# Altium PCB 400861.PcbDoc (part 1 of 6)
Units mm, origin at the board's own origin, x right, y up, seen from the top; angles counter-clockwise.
Board outline 145 x 63.5 mm, 8 copper layers (Top Side, Mid-Layer 1, Mid-Layer 2, Mid-Layer 3, Mid-Layer 4, Mid-Layer 5, Mid-Layer 6, Bottom Side), stack 1.529 mm thick; 284 components, 233 nets, 1158 pads, 3522 vias.
Unrouted connection lines stored in the file: 1.
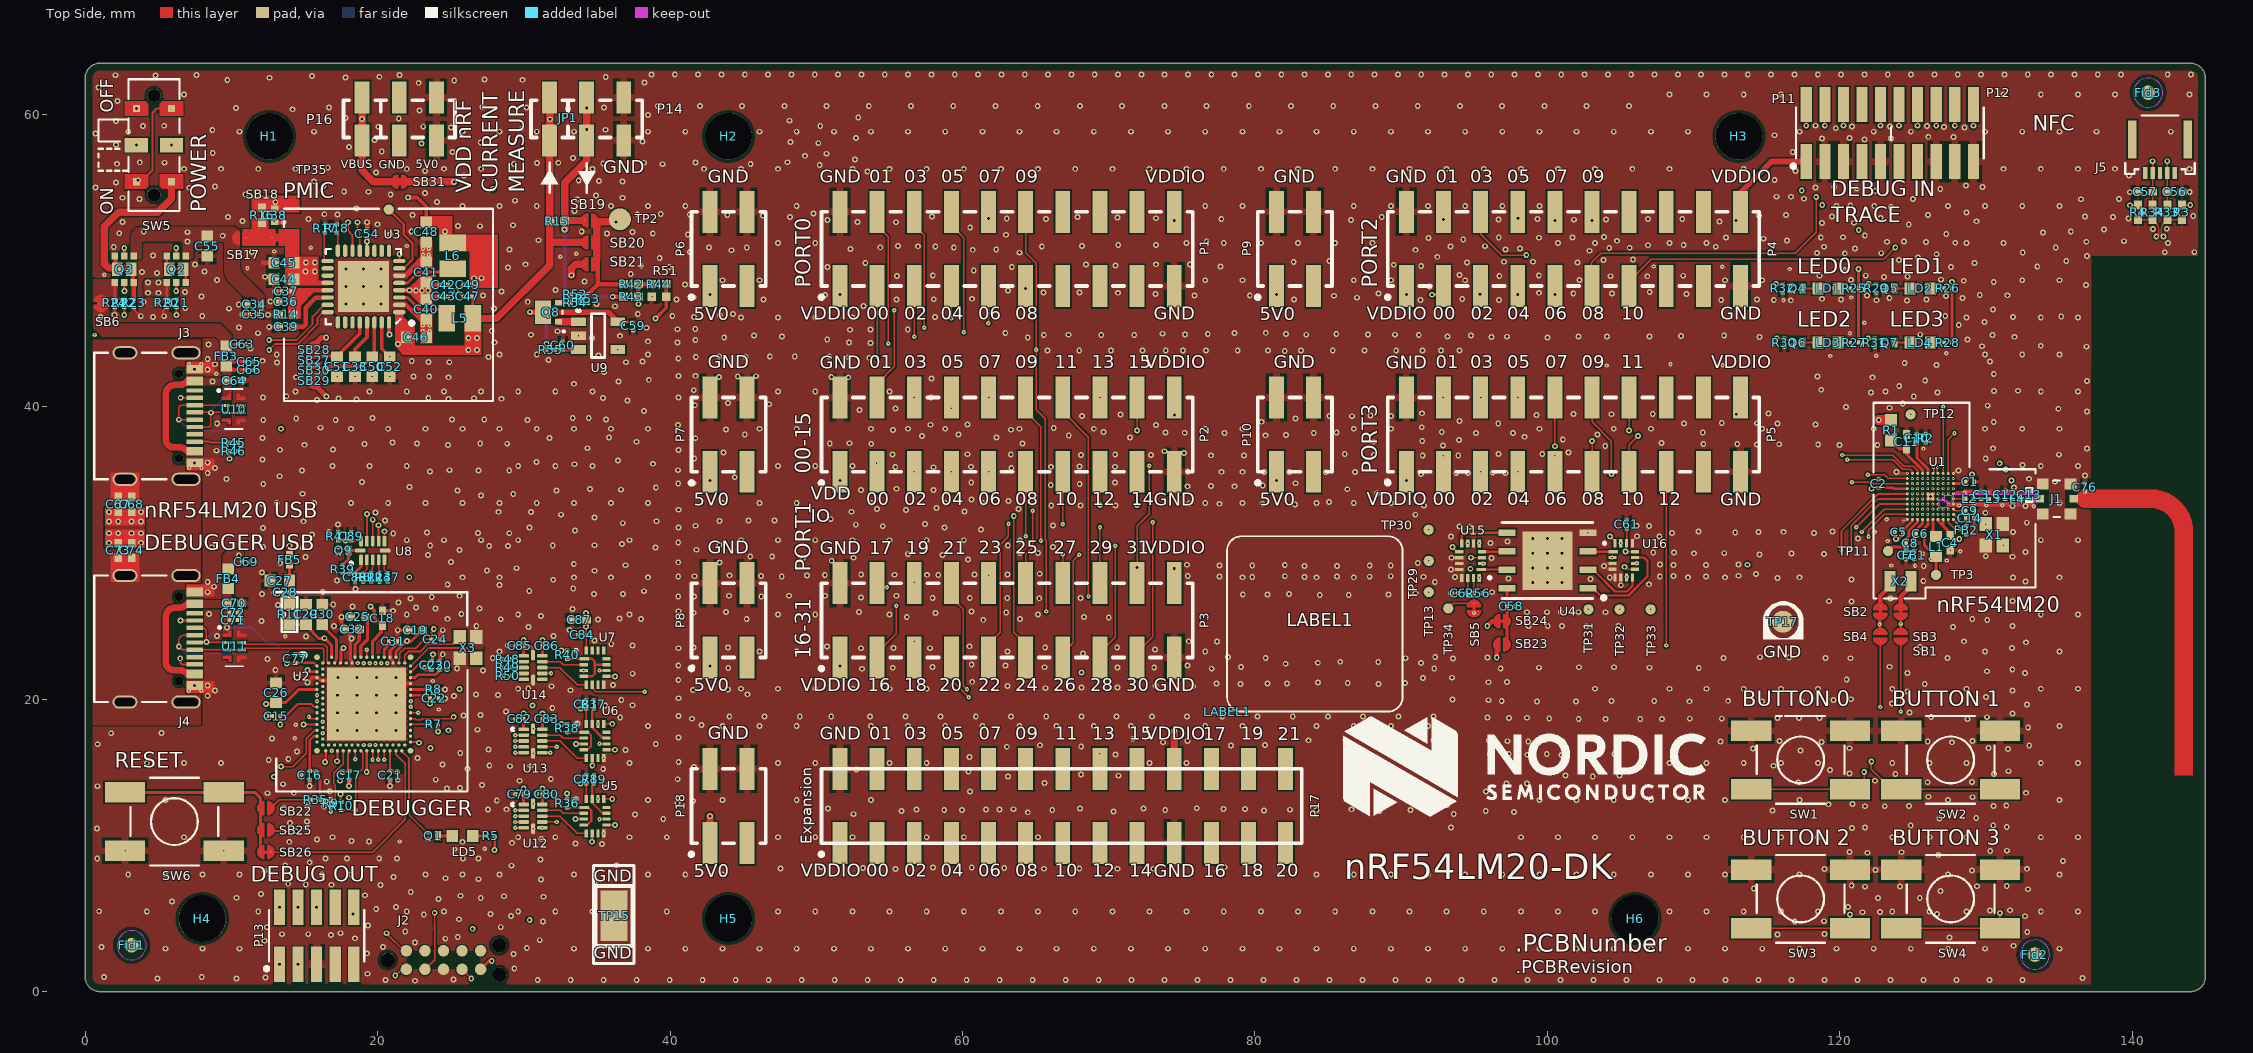
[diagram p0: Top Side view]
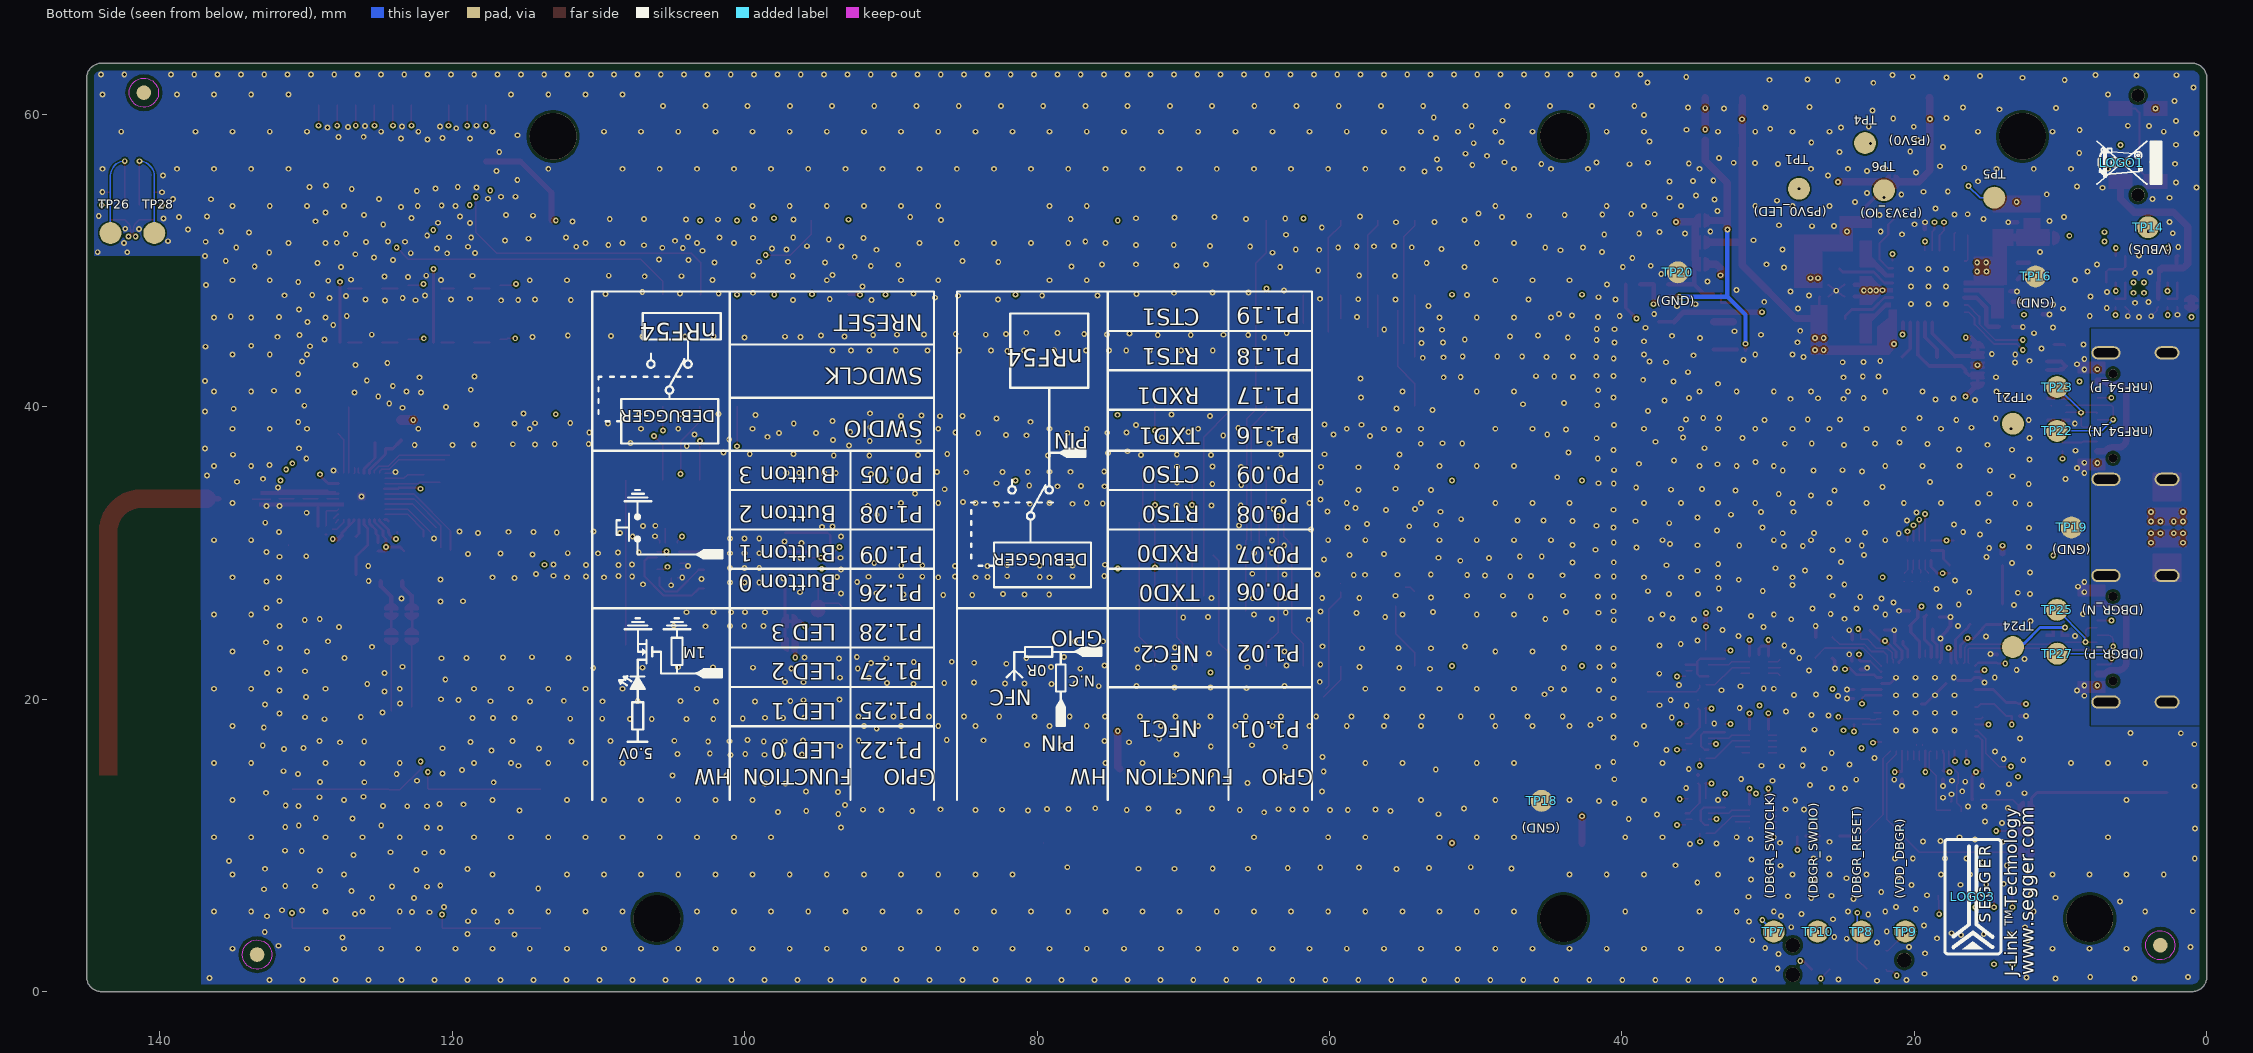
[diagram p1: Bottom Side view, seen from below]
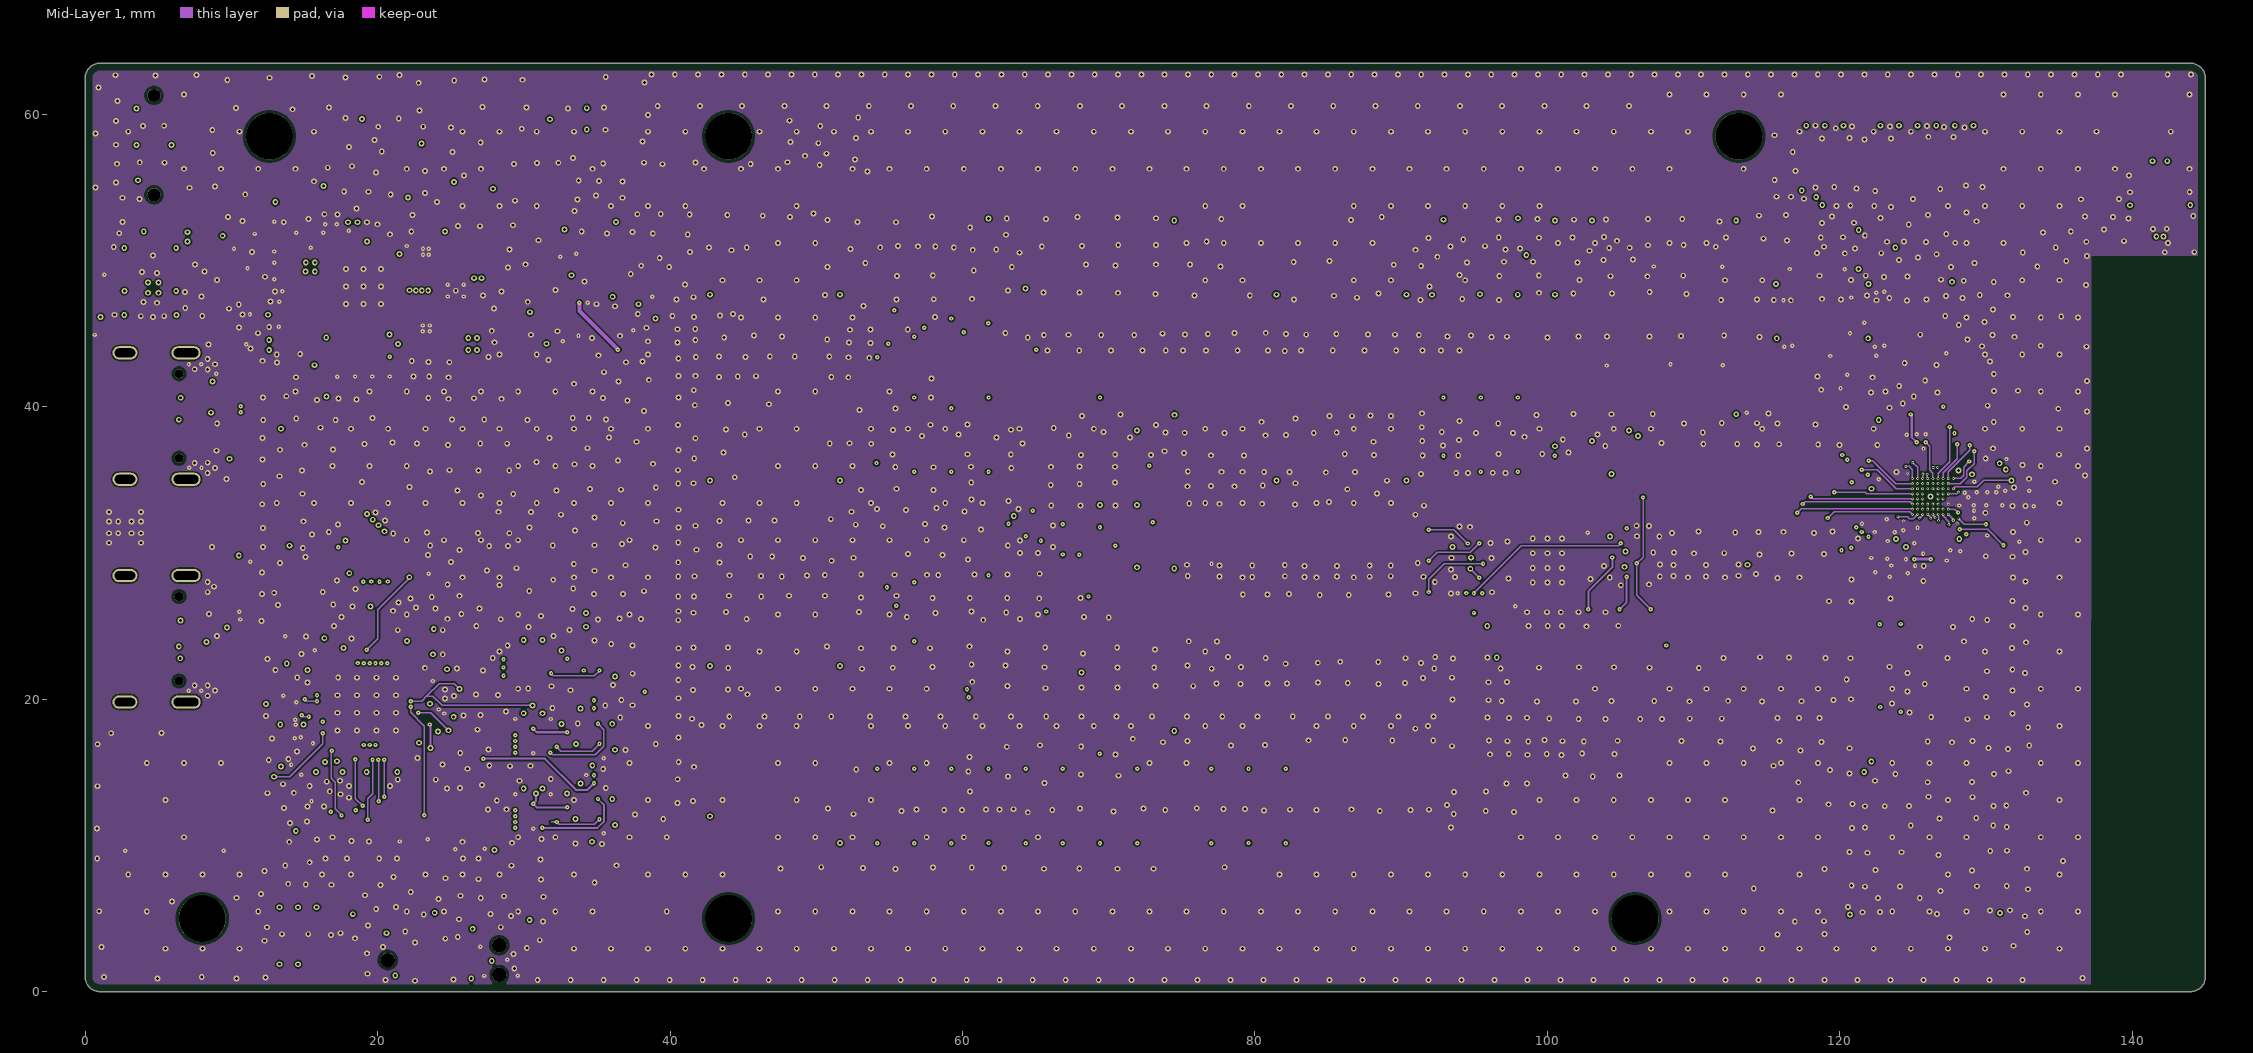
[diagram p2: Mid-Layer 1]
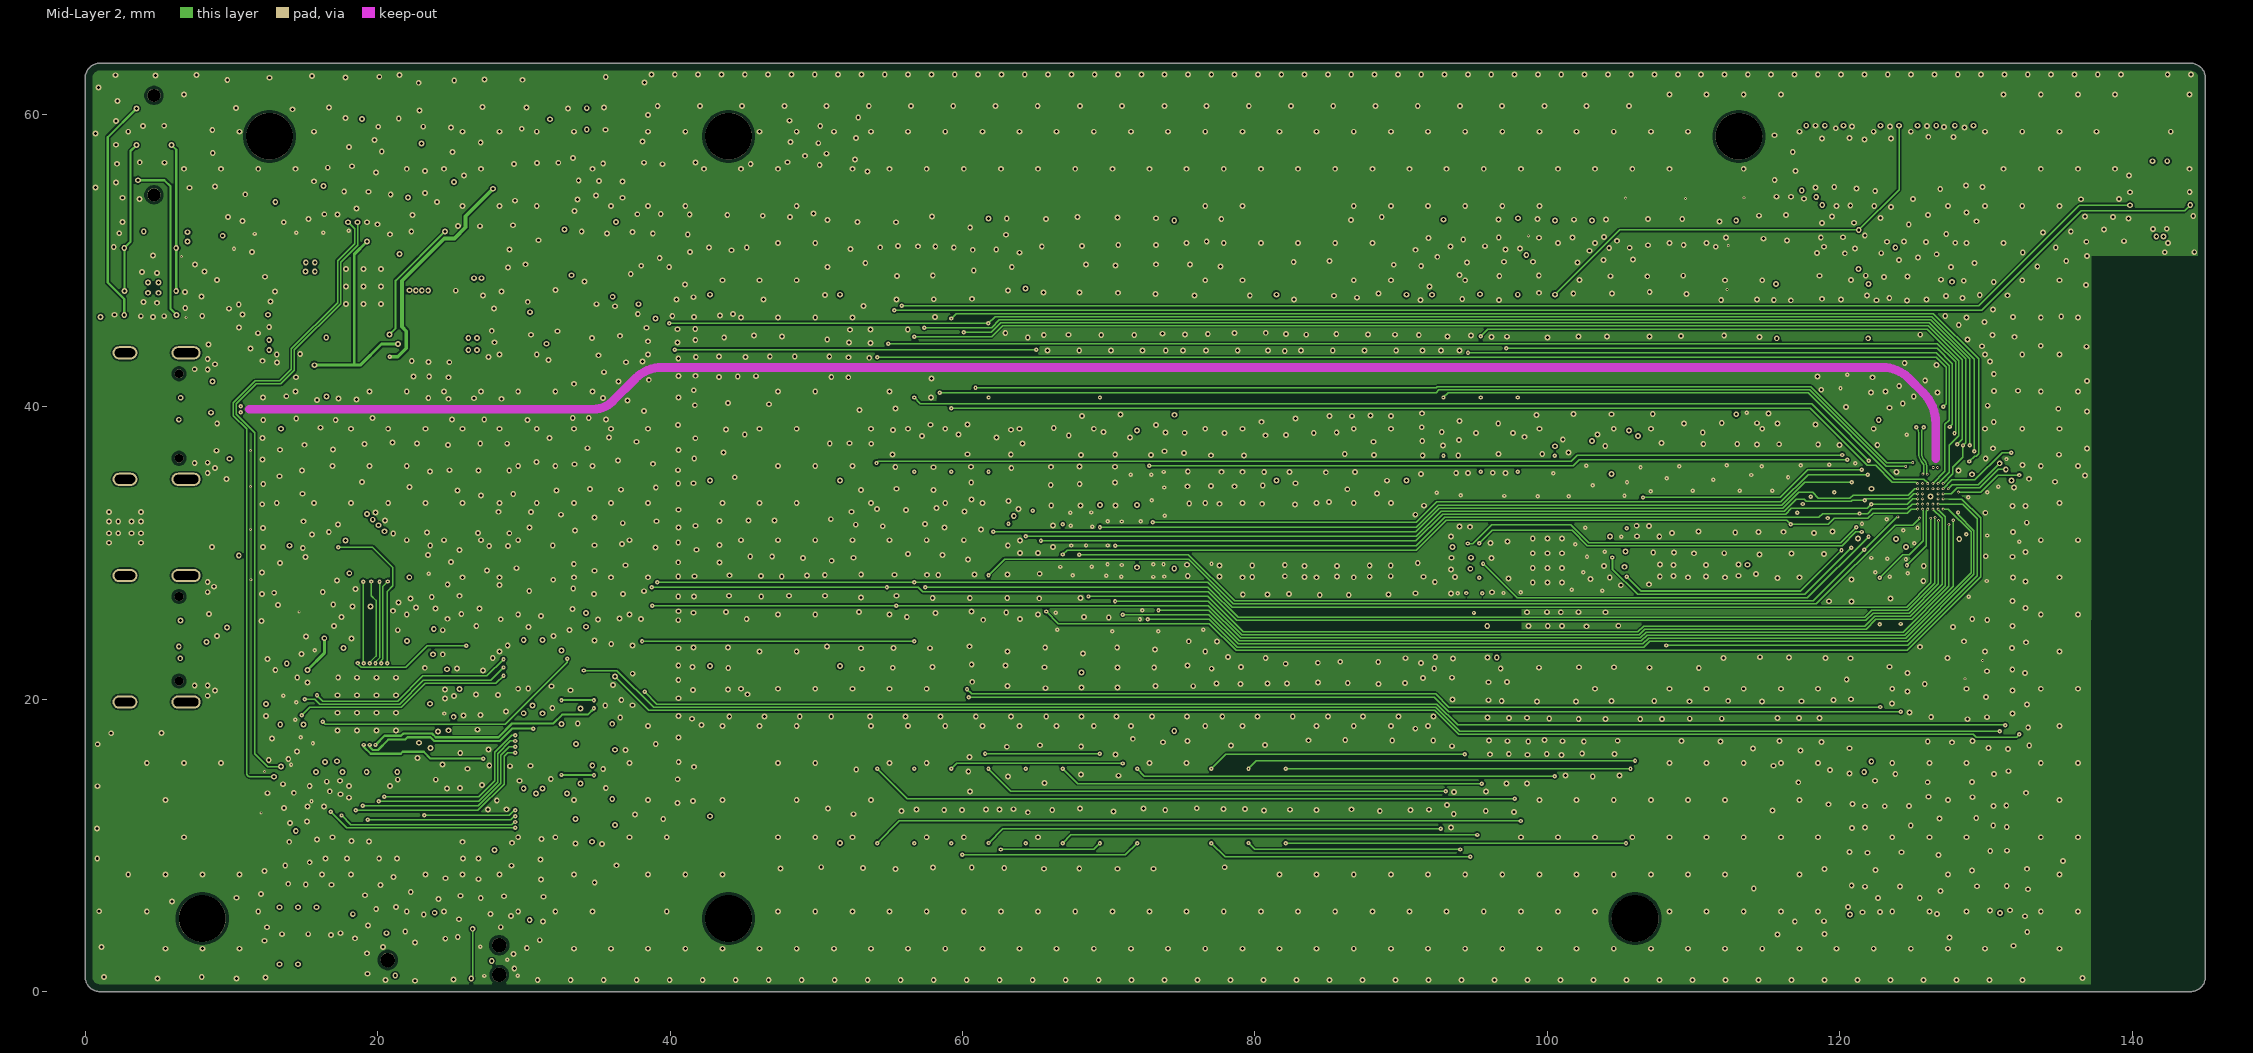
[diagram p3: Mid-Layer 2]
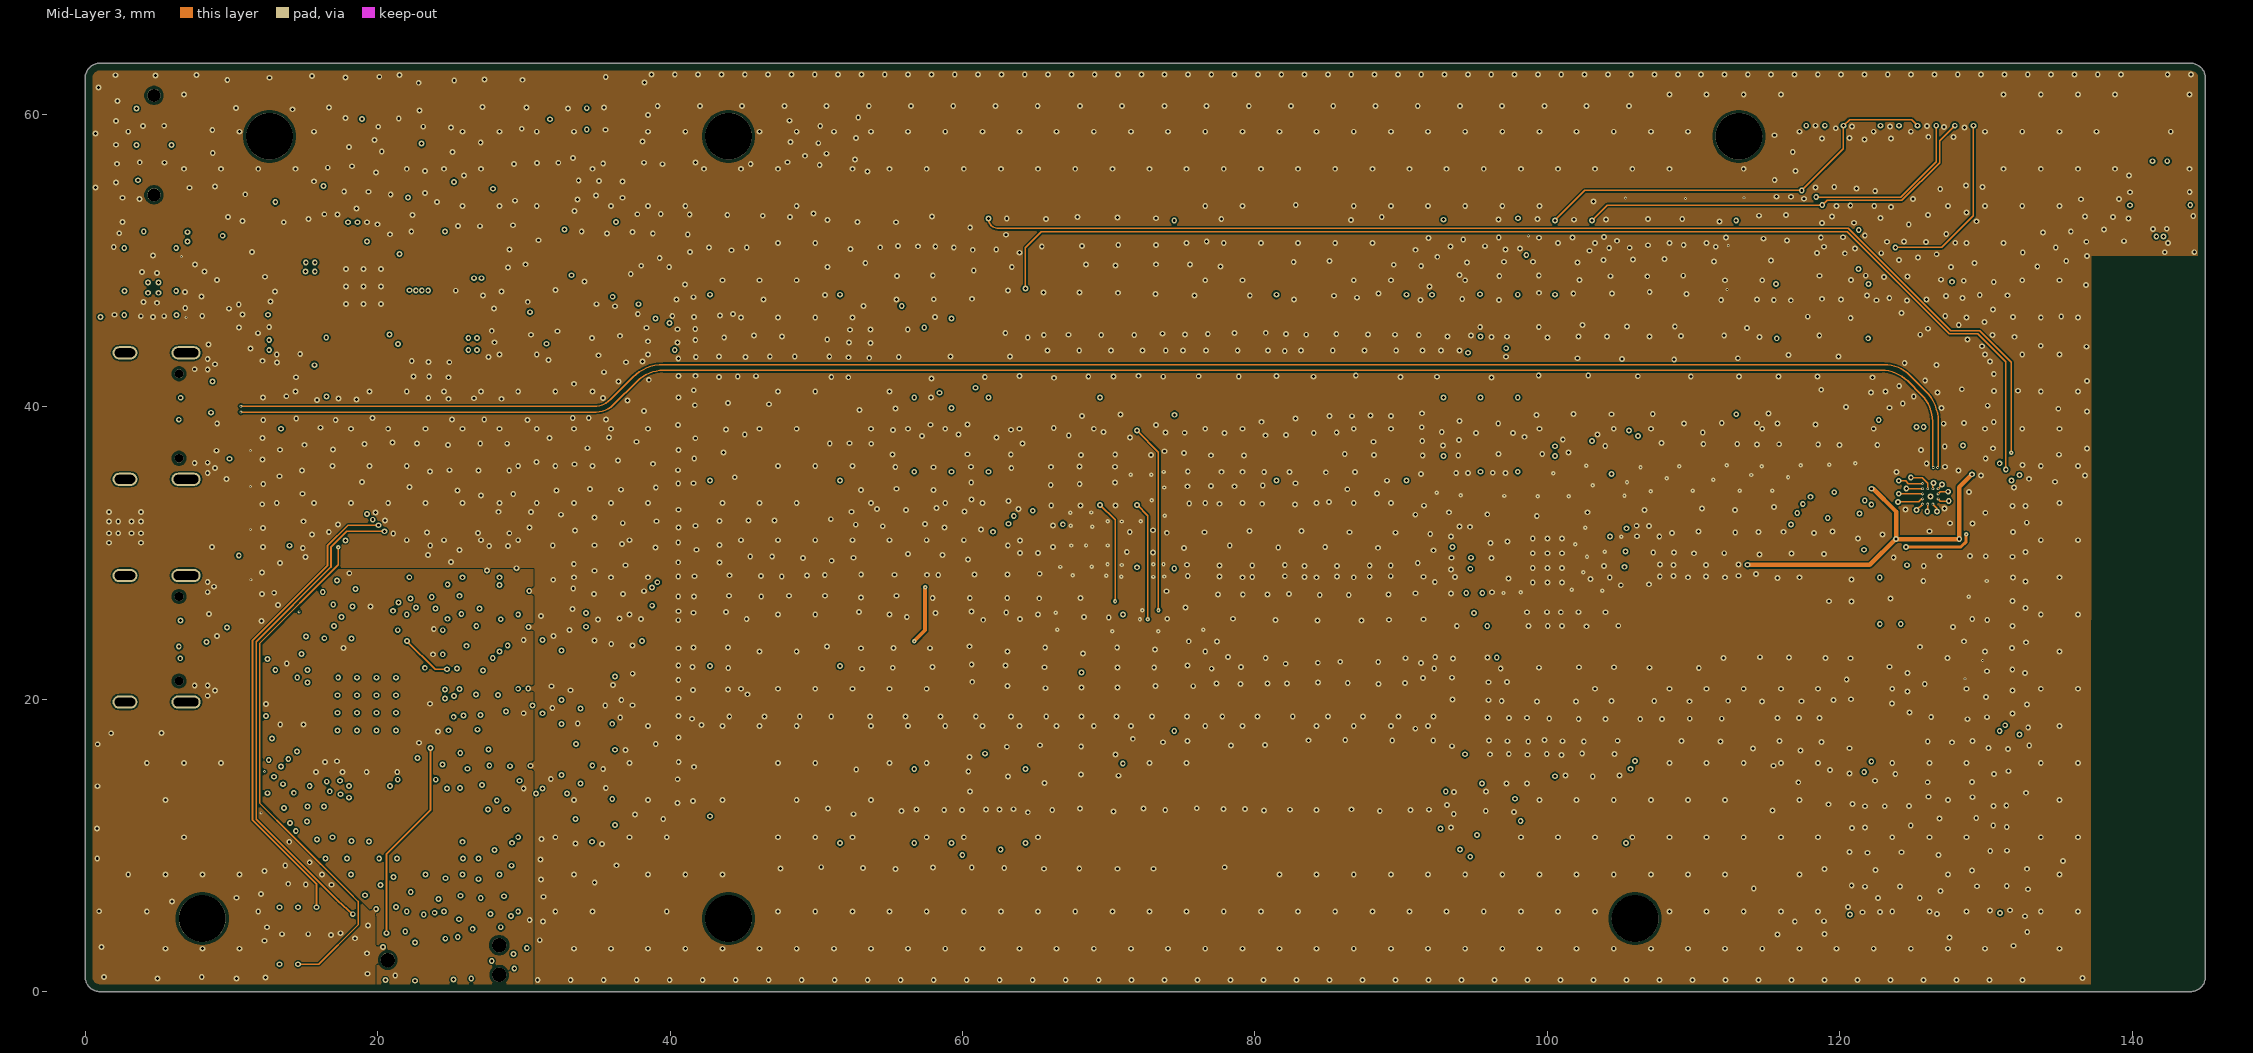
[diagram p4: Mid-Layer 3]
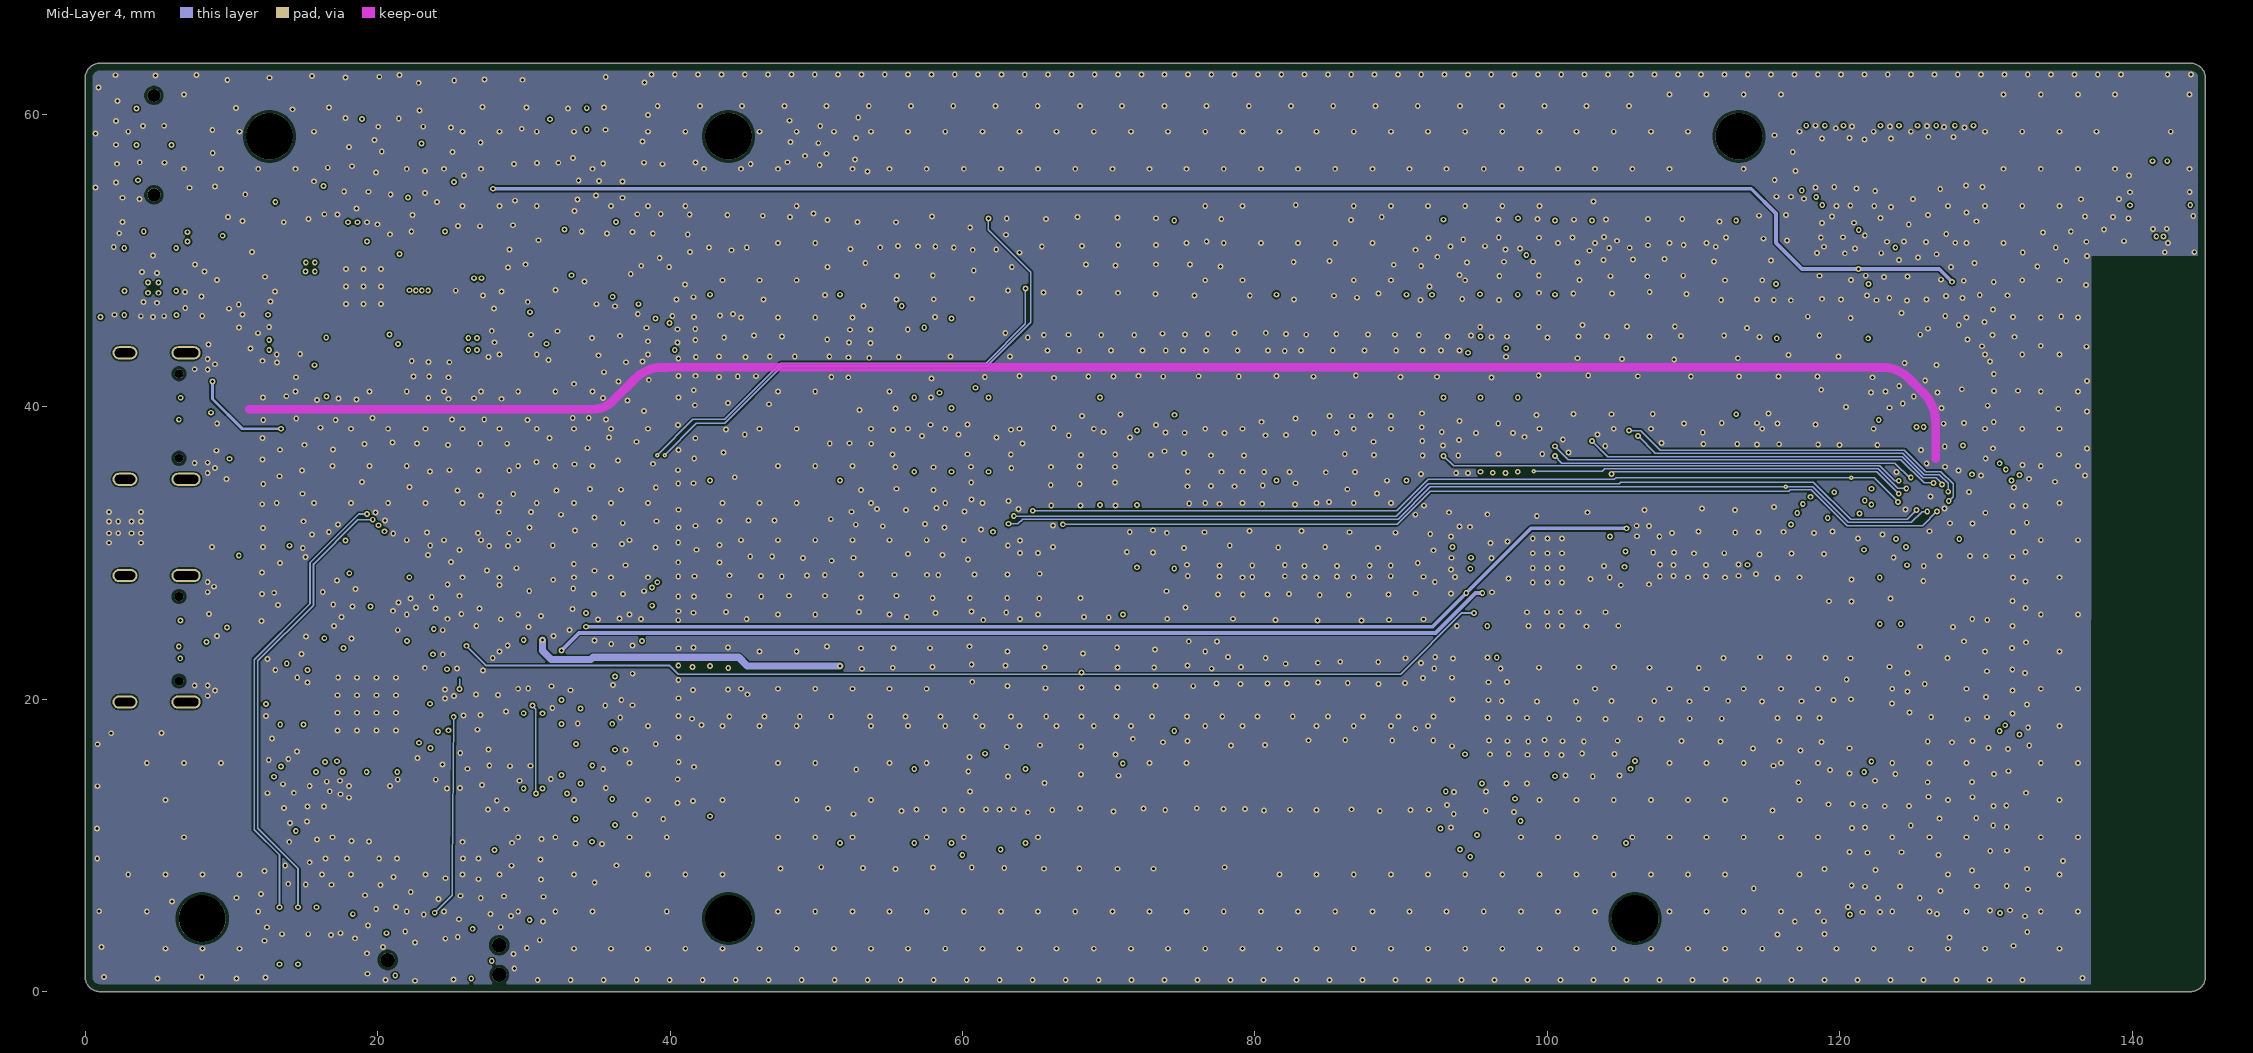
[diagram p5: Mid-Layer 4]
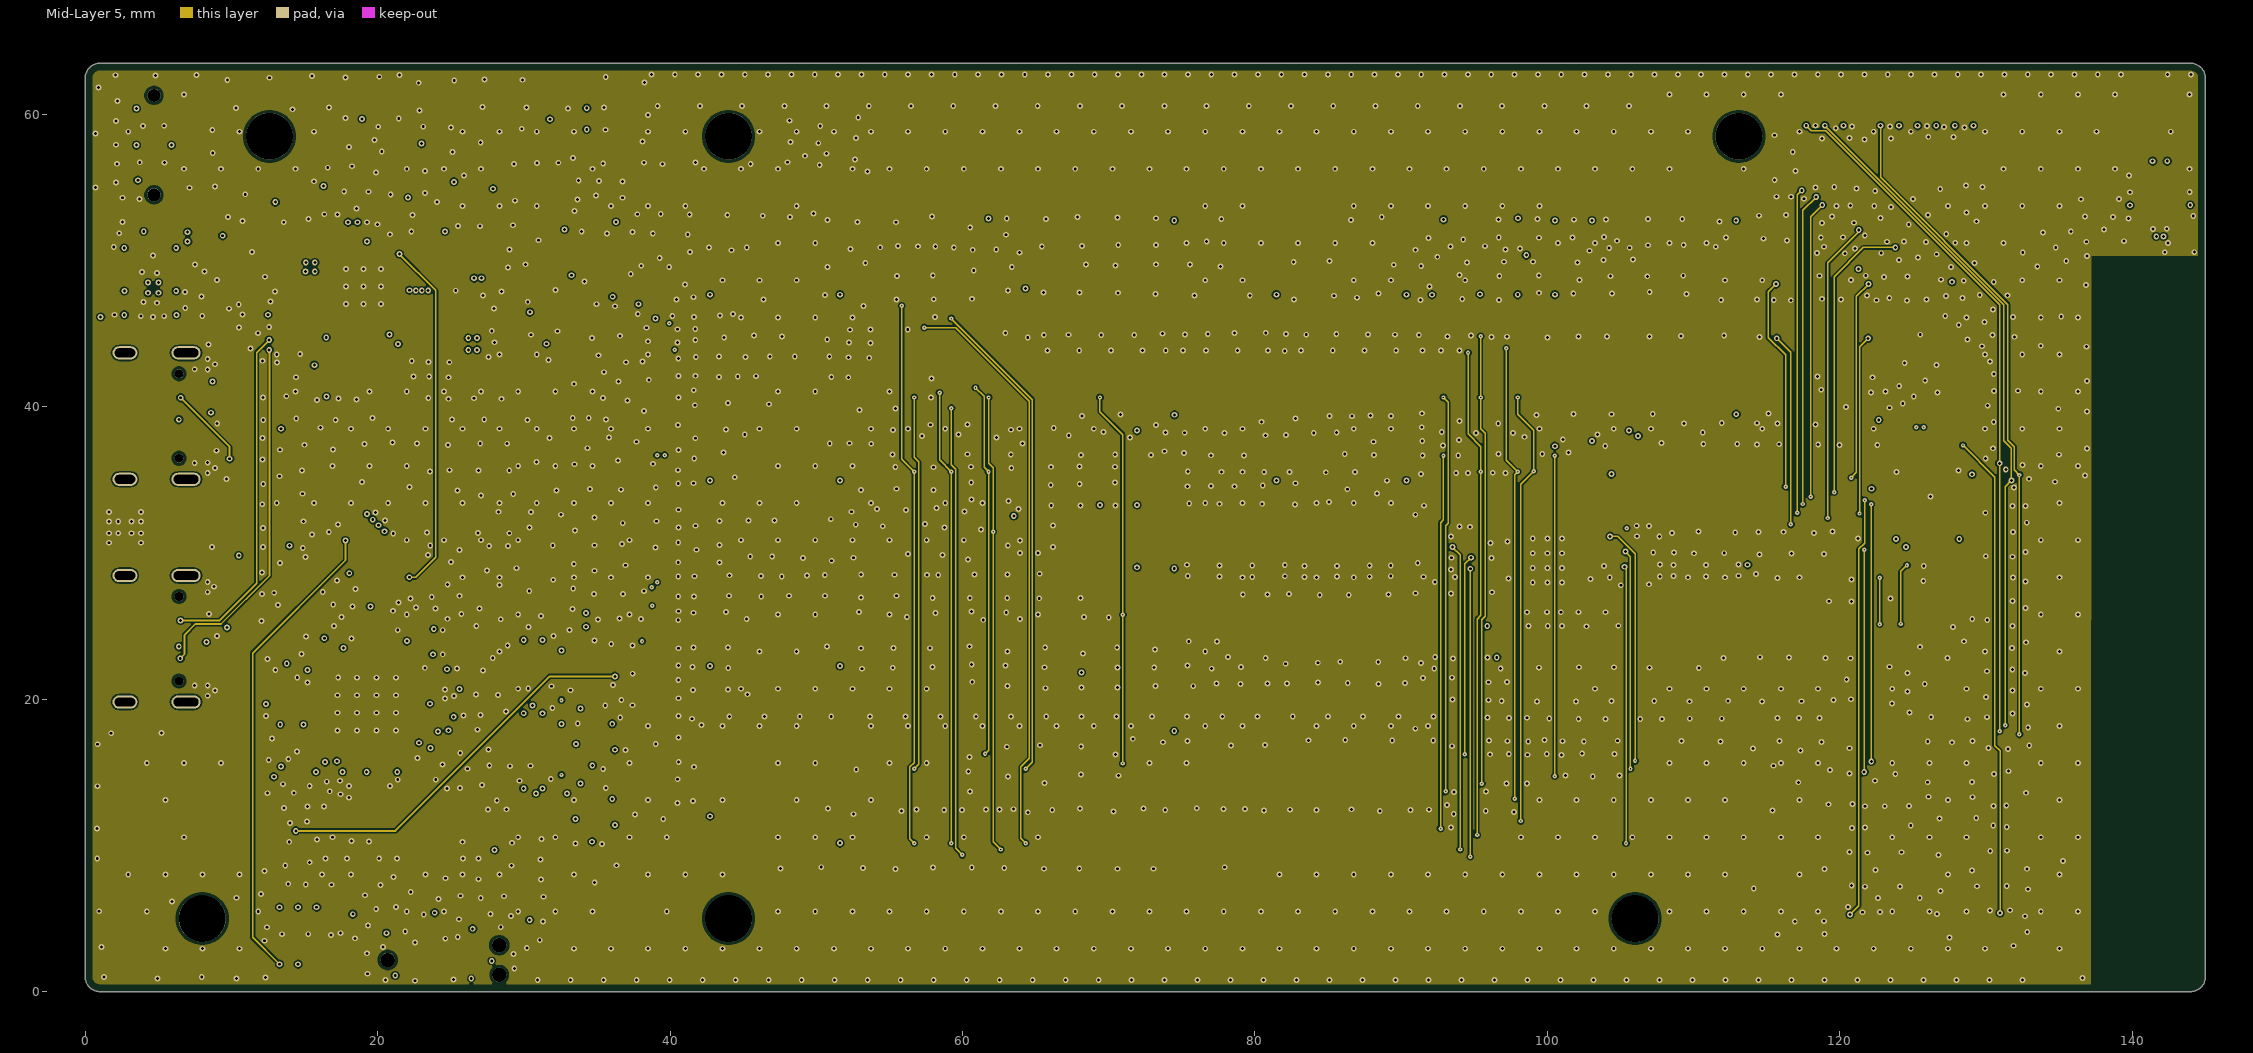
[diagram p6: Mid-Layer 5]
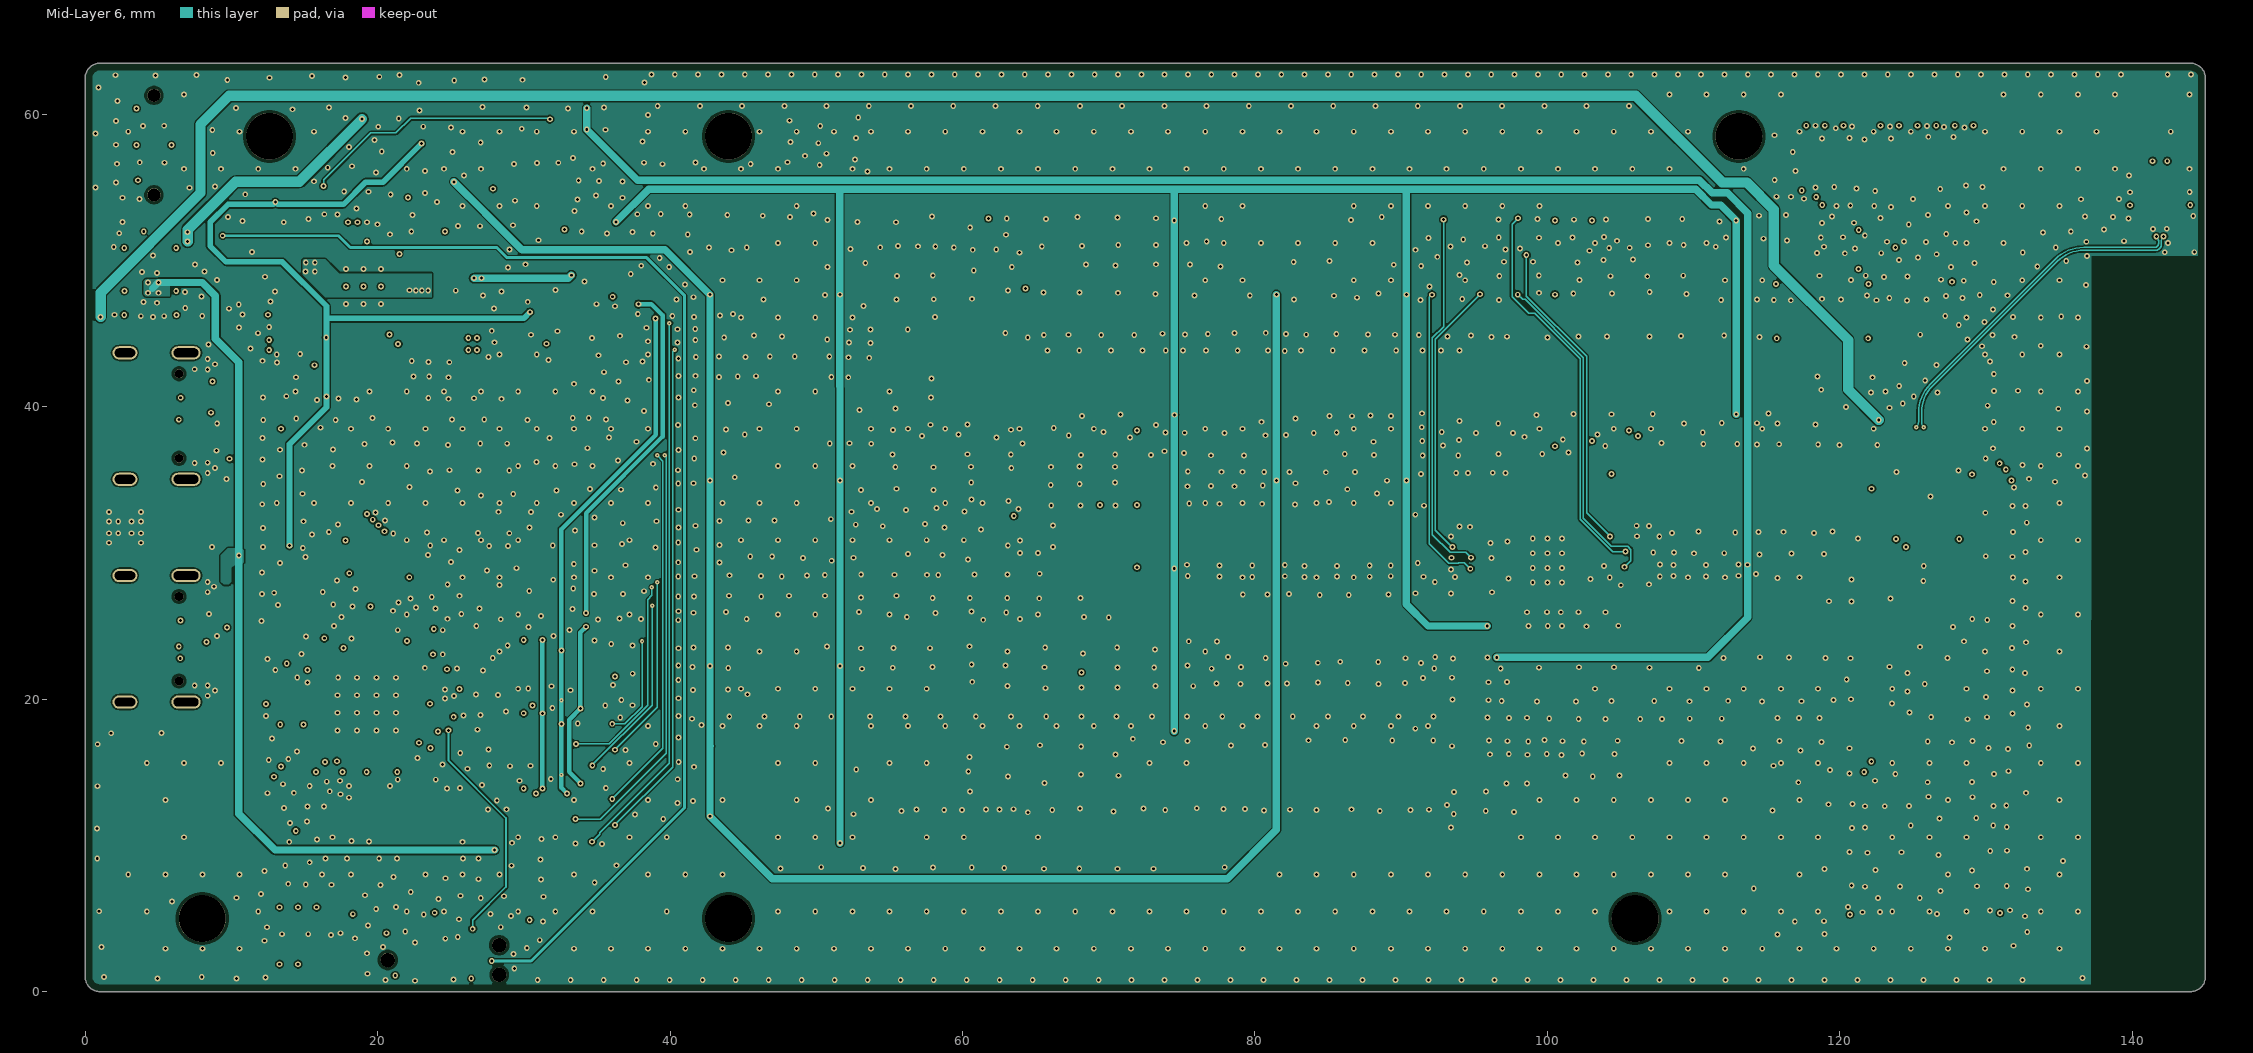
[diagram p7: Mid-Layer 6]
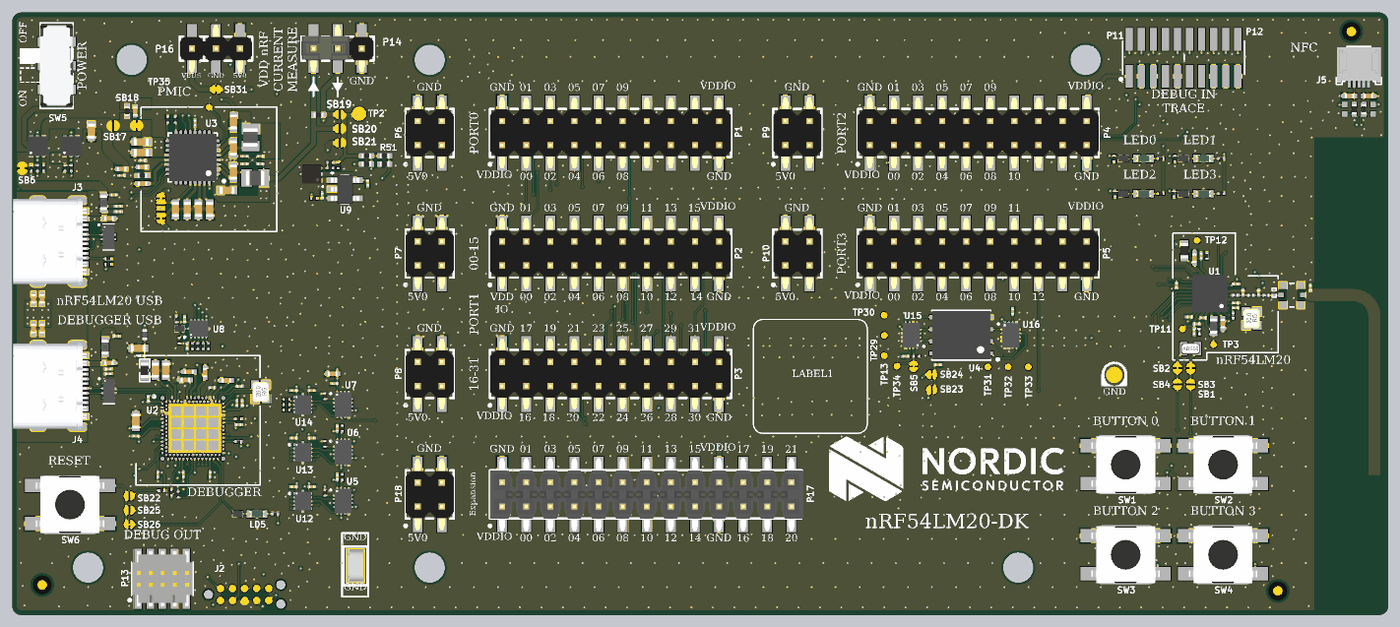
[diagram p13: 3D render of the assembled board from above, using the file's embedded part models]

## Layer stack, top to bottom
Top Solder: solder mask 0.015, WE-SM-0001, Dk 3.3
Top Side: signal copper 0.035
Dielectric 1: prepreg 0.07, WE-PP-0034, Dk 4.3
Mid-Layer 1: signal copper 0.025
Dielectric 2: prepreg 0.07, WE-PP-0034, Dk 4.3
Mid-Layer 2: signal copper 0.025
Dielectric 3: prepreg 0.07, WE-PP-0034, Dk 4.3
Mid-Layer 3: signal copper 0.025
Core 1: core 0.889, Core-041, Dk 4.8
Mid-Layer 4: signal copper 0.025
Dielectric 4: prepreg 0.07, WE-PP-0034, Dk 4.3
Mid-Layer 5: signal copper 0.025
Dielectric 5: prepreg 0.07, WE-PP-0034, Dk 4.3
Mid-Layer 6: signal copper 0.025
Dielectric 6: prepreg 0.07, WE-PP-0034, Dk 4.3
Bottom Side: signal copper 0.035
Bottom Solder: solder mask 0.015, WE-SM-0001, Dk 3.3

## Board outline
0,1 0,62.5 cw(c1,62.5) 1,63.5 144.002,63.5 144.002,63.499 cw(c144.002,62.5) 145,62.5 145,1 cw(c144,1) 144,0 1.001,0 1,0 cw(c1,1)

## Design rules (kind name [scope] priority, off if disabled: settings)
BoardOutlineClearance [All] p1: gap=0.25 ignorepadtopadclearanceinfootprint=FALSE except(0: Arc-SplitContinuation Track-SplitContinuation SMDPad-SplitContinuation THPad-SplitContinuation Via-SplitContinuation Fill-SplitContinuation Poly-SplitContinuation Region-SplitContinuation Text-SplitContinuation; 0.5: Arc-OutlineEdge Track-OutlineEdge SMDPad-OutlineEdge THPad-OutlineEdge Via-OutlineEdge Fill-OutlineEdge Poly-OutlineEdge Region-OutlineEdge Text-OutlineEdge)
Clearance Clearance_fid [InComponent('Fid1')or InComponent('Fid2')or InComponent('Fid3')] p1: gap=0.1 ignorepadtopadclearanceinfootprint=FALSE except(0.25: Arc-Fill Arc-Poly Arc-Region Track-Fill Track-Poly Track-Region SMDPad-Fill SMDPad-Poly SMDPad-Region THPad-Fill THPad-Poly THPad-Region Via-Fill Via-Poly Via-Region Fill-Fill Fill-Poly Fill-Region Poly-Poly Poly-Region Region-Region)
Clearance Clearance_keepout [IsKeepOut] p2: gap=0 ignorepadtopadclearanceinfootprint=FALSE
Clearance Clearance_54L20_room [InComponentClass('nRF54L20')] p3: gap=0.09 ignorepadtopadclearanceinfootprint=FALSE
Clearance "Antenna RF path clearance" [InNetClass('RF')] p4: gap=0.108 ignorepadtopadclearanceinfootprint=FALSE
Clearance "GND polygons" [InPolygonClass('GND')] p5: gap=0.15 ignorepadtopadclearanceinfootprint=FALSE
Clearance Clearance_NPTH [(HoleDiameter > 0) and (PadIsPlated = 'False')] p6: gap=0.254 ignorepadtopadclearanceinfootprint=FALSE except(0.2: Arc-Hole Track-Hole SMDPad-THPad SMDPad-Hole Fill-Hole Poly-Hole Region-Hole)
Clearance "Schematic Clearance Constraint_5" [InComponent('H6')] p7: gap=0.254 ignorepadtopadclearanceinfootprint=TRUE except(0: Arc-Hole Track-Hole SMDPad-Hole THPad-Hole Via-Hole Fill-Hole Poly-Hole Region-Hole Text-Hole)
Clearance "Schematic Clearance Constraint_4" [InComponent('H1')] p8: gap=0.254 ignorepadtopadclearanceinfootprint=TRUE except(0: Arc-Hole Track-Hole SMDPad-Hole THPad-Hole Via-Hole Fill-Hole Poly-Hole Region-Hole Text-Hole)
Clearance "Schematic Clearance Constraint_3" [InComponent('H4')] p9: gap=0.254 ignorepadtopadclearanceinfootprint=TRUE except(0: Arc-Hole Track-Hole SMDPad-Hole THPad-Hole Via-Hole Fill-Hole Poly-Hole Region-Hole Text-Hole)
Clearance "Schematic Clearance Constraint_2" [InComponent('H3')] p10: gap=0.254 ignorepadtopadclearanceinfootprint=TRUE except(0: Arc-Hole Track-Hole SMDPad-Hole THPad-Hole Via-Hole Fill-Hole Poly-Hole Region-Hole Text-Hole)
Clearance "Schematic Clearance Constraint_1" [InComponent('H2')] p11: gap=0.254 ignorepadtopadclearanceinfootprint=TRUE except(0: Arc-Hole Track-Hole SMDPad-Hole THPad-Hole Via-Hole Fill-Hole Poly-Hole Region-Hole Text-Hole)
Clearance "Schematic Clearance Constraint" [InComponent('H5')] p12: gap=0.254 ignorepadtopadclearanceinfootprint=TRUE except(0: Arc-Hole Track-Hole SMDPad-Hole THPad-Hole Via-Hole Fill-Hole Poly-Hole Region-Hole Text-Hole)
Clearance [All] p13: gap=0.1 ignorepadtopadclearanceinfootprint=FALSE except(0: Region-Region; 0.051: Text-Text)
ComponentClearance "Jumper clearance" [All] p1 off: gap=0 collisioncheckmode=3 verticalgap=0 showdistances=FALSE checkcomponentboundary=TRUE
ComponentClearance "Solder bridge overlap" [All] p2 off: gap=0.254 collisioncheckmode=3 verticalgap=2540 showdistances=FALSE donotcheckwithout3dbody=TRUE checkcomponentboundary=TRUE
ComponentClearance [All] p3 off: gap=0 collisioncheckmode=3 verticalgap=2540 showdistances=TRUE
DiffPairsRouting DiffPairsRouting_NFC [InDifferentialPair('NFC')] p1: maxlimit=0.4 minlimit=0.1 mostfreqgap=0.1 toplayer_minwidth=0.1 toplayer_maxwidth=0.5 toplayer_prefwidth=0.1 midlayer1_minwidth=0.1 midlayer1_maxwidth=0.5 midlayer1_prefwidth=0.1 midlayer2_minwidth=0.1 midlayer2_maxwidth=0.5 midlayer2_prefwidth=0.1 midlayer3_minwidth=0.1 midlayer3_maxwidth=0.5 midlayer3_prefwidth=0.1 midlayer4_minwidth=0.1 midlayer4_maxwidth=0.5 midlayer4_prefwidth=0.1 midlayer5_minwidth=0.1 midlayer5_maxwidth=0.5 midlayer5_prefwidth=0.1 midlayer6_minwidth=0.1 midlayer6_maxwidth=0.5 midlayer6_prefwidth=0.1 bottomlayer_minwidth=0.1 bottomlayer_maxwidth=0.5 bottomlayer_prefwidth=0.1 maxuncoupledlength=12.7
DiffPairsRouting DiffPairsRouting_USB [InNetClass('USB')] p2: maxlimit=0.3 minlimit=0.127 mostfreqgap=0.3 toplayer_maxgap=0.127 toplayer_prefgap=0.127 toplayer_minwidth=0.099 toplayer_maxwidth=0.099 toplayer_prefwidth=0.099 midlayer1_maxgap=0.127 midlayer1_prefgap=0.127 midlayer1_minwidth=0.049 midlayer1_maxwidth=0.049 midlayer1_prefwidth=0.049 midlayer2_maxgap=0.127 midlayer2_prefgap=0.127 midlayer2_minwidth=0.049 midlayer2_maxwidth=0.049 midlayer2_prefwidth=0.049 midlayer3_mingap=0.3 midlayer3_minwidth=0.09 midlayer3_maxwidth=0.09 midlayer3_prefwidth=0.09 midlayer4_mingap=0.3 midlayer4_minwidth=0.09 midlayer4_maxwidth=0.09 midlayer4_prefwidth=0.09 midlayer5_maxgap=0.127 midlayer5_prefgap=0.127 midlayer5_minwidth=0.049 midlayer5_maxwidth=0.049 midlayer5_prefwidth=0.049 midlayer6_maxgap=0.127 midlayer6_prefgap=0.127 midlayer6_minwidth=0.049 midlayer6_maxwidth=0.049 midlayer6_prefwidth=0.049 bottomlayer_maxgap=0.127 bottomlayer_prefgap=0.127 bottomlayer_minwidth=0.099 bottomlayer_maxwidth=0.099 bottomlayer_prefwidth=0.099 impedanceprofiledriven=TRUE impedanceprofileid={92417A29-2017-4163-8AF2-36A2DA04E51D} impedanceprofilevalue=90.000000 maxuncoupledlength=12.7
Height [All] p1 off: minheight=0 maxheight=25.4 prefheight=12.7
HoleSize [All] p1: absolutevalues=TRUE maxlimit=5 minlimit=0.025 maxpercent=80.000 minpercent=20.000
HoleToHoleClearance HoleToHoleClearance_nRF54 [WithinRoom('nRF54L20')] p1: gap=0.1 allowstackedmicrovias=TRUE
HoleToHoleClearance [All] p2: gap=0.15 allowstackedmicrovias=TRUE
MatchedLengths "Schematic Matched Net Lengths" [InNetClass('TRACE')] p1: tolerance=25.4 checknetsindiffpair=FALSE checkdiffpairvsdiffpair=TRUE checkxsignals=TRUE checkothers=TRUE usedelayunits=TRUE delaytolerance=500.000000
MinimumSolderMaskSliver [All] p1: minsoldermaskwidth=0.1
PolygonConnect "VBUS polygons" [InNet('VBUS') or InNet('VBUS_nRF') or InNet('VBUS_DBGR')] p1: connectstyle=Direct reliefconductorwidth=0.25 reliefentries=4 polygonreliefangle="90 Angle" airgapwidth=0.15
PolygonConnect "GND Polygon and Vias" [IsVia and InNet('GND')] p2: connectstyle=Direct reliefconductorwidth=0.254 reliefentries=4 polygonreliefangle="90 Angle" airgapwidth=0.254
PolygonConnect "GND Polygon and connectors" [InNet('GND') and InComponent('P*')] p3: connectstyle=Relief reliefconductorwidth=0.5 reliefentries=4 polygonreliefangle="90 Angle" conductorbypadedge=TRUE mindistance=0.25 enablemindistance=TRUE airgapwidth=0.2
PolygonConnect "GND Polygon and switches" [InNet('GND') and InComponent('SW*')] p4: connectstyle=Relief reliefconductorwidth=0.5 reliefentries=4 polygonreliefangle="90 Angle" conductorbypadedge=TRUE mindistance=0.25 enablemindistance=TRUE airgapwidth=0.2
PolygonConnect PolygonConnect_1 [IsPad and not InNet('GND') vs IsPolygon] p5: connectstyle=Direct reliefconductorwidth=0.254 reliefentries=4 polygonreliefangle="90 Angle" airgapwidth=0.254
PolygonConnect "GND Polygon and components" [InNet('GND') and InComponent('R*') or InComponent('C*') or InNamedPolygon('GND_nRF54')] p6: connectstyle=Relief reliefconductorwidth=0.3 reliefentries=4 polygonreliefangle="90 Angle" conductorbypadedge=TRUE mindistance=0.25 enablemindistance=TRUE airgapwidth=0.2
PolygonConnect [All] p7: connectstyle=Direct reliefconductorwidth=0.254 reliefentries=4 polygonreliefangle="90 Angle" airgapwidth=0.254
RoomDefinition Flash [InComponentClass('Flash')] p1: confinementstyle=ConfineIn formatcopy=TRUE lockcomponents=FALSE outline 94.28,17.972 94.28,20.772 95.926,20.772 95.926,21.147 96.451,21.147 96.451,25.647 104.181,25.647 104.181,19.997 95.683,19.997 95.683,17.972
RoomDefinition nRF54 [InComponentClass('nRF54')] p2: confinementstyle=ConfineIn formatcopy=TRUE lockcomponents=FALSE outline 123.856,31.657 128.476,31.657 128.476,36.5 123.856,36.5
RoomDefinition "Power Switch" [InComponentClass('Power Switch')] p3: confinementstyle=ConfineIn formatcopy=TRUE lockcomponents=FALSE outline -0.056,53.17 -0.056,62.831 9.156,62.831 9.156,49.279 12.679,49.279 12.679,46.721 6.779,46.721 6.779,46.302 6.104,46.302 3.854,46.302 3.209,46.302 2.141,46.302 1.486,46.302 1.486,47.557 0.816,47.557 0.816,53.17
RoomDefinition "Current measurments" [InComponentClass('Current measurments')] p4: confinementstyle=ConfineIn formatcopy=TRUE lockcomponents=FALSE outline 30.081,58.98 30.081,62.231 30.109,62.231 30.109,63.351 38.491,63.351 38.491,57.52 33.505,57.52 33.505,55.695 31.095,55.695 31.095,57.52 30.109,57.52 30.109,58.98
RoomDefinition nPM1300 [InComponentClass('nPM1300')] p5: confinementstyle=ConfineIn formatcopy=TRUE lockcomponents=FALSE outline 9.694,50.696 9.694,52.404 11.395,52.404 11.395,54.306 13.25,54.306 13.25,55.585 20.794,55.585 20.794,56.093 22.089,56.093 22.089,59.318 24.647,59.318 24.647,56.194 29.168,56.194 29.168,53.636 27.591,53.636 27.591,44.568 24.129,44.568 24.129,43.946 20.805,43.946 20.805,41.695 20.604,41.695 20.604,40.64 18.396,40.64 18.396,41.521 18.271,41.521 18.271,42.396 15.946,42.396 15.946,44.821 12.527,44.821 12.527,45.816 10.771,45.816 10.771,46.346 10.446,46.346 10.446,50.696
RoutingVias RoutingVia_RF54L20 [WithinRoom('nRF54')] p1: holewidth=0.711 width=1.27 viastyle="Through Hole" minholewidth=0.711 minwidth=1.27 maxholewidth=0.711 maxwidth=1.27 useviatemplates=TRUE viatemplateguid#1={EEEC76CF-32D6-49DC-93D9-2D917E6DBA36} viatemplateguid#2={30F8C89D-5C5B-4339-859E-098A5C8AA5FD} viatemplateguid#3={3D985D34-457C-4E2A-A3DE-9B1BD65E1015} viatemplatename#1=v20h10 viatemplatename#2=v30h10m0 viatemplatename#3=v40h20m0mx0
RoutingVias RoutingVia_Blind [IsBlindVia] p2: holewidth=0.711 width=1.27 viastyle="Through Hole" minholewidth=0.711 minwidth=1.27 maxholewidth=0.711 maxwidth=1.27 useviatemplates=TRUE viatemplateguid#1={30F8C89D-5C5B-4339-859E-098A5C8AA5FD} viatemplatename#1=v30h10m0
RoutingVias RoutingVia_Burried [InDrillLayerPair('Mid-Layer 3 - Mid-Layer 4')] p3: holewidth=0.711 width=1.27 viastyle="Through Hole" minholewidth=0.711 minwidth=1.27 maxholewidth=0.711 maxwidth=1.27 useviatemplates=TRUE viatemplateguid#1={3D985D34-457C-4E2A-A3DE-9B1BD65E1015} viatemplatename#1=v40h20m0mx0
RoutingVias RoutingVia_Burried_laser [InDrillLayerPair('Mid-Layer 1 - Mid-Layer 2') or  InDrillLayerPair('Mid-Layer 2 - Mid-Layer 3') or InDrillLayerPair('Mid-Layer 4 - Mid-Layer 5') or  InDrillLayerPair('Mid-Layer 5 - Mid-Layer 6')] p4: holewidth=0.711 width=1.27 viastyle="Through Hole" minholewidth=0.711 minwidth=1.27 maxholewidth=0.711 maxwidth=1.27 useviatemplates=TRUE viatemplateguid#1={30F8C89D-5C5B-4339-859E-098A5C8AA5FD} viatemplatename#1=v30h10m0
RoutingVias RoutingVia_Thru [IsThruVia] p5: holewidth=0.25 width=0.5 viastyle="Through Hole" minholewidth=0.1 minwidth=0.2 maxholewidth=0.5 maxwidth=1.2 useviatemplates=TRUE viatemplateguid#1={3D985D34-457C-4E2A-A3DE-9B1BD65E1015} viatemplatename#1=v40h20m0mx0
RoutingVias "Schematic Routing Via Style_5" [InComponent('H5')] p6: holewidth=0 width=0 viastyle="Through Hole" minholewidth=0 minwidth=0 maxholewidth=2 maxwidth=2
RoutingVias "Schematic Routing Via Style_4" [InComponent('H1')] p7: holewidth=0 width=0 viastyle="Through Hole" minholewidth=0 minwidth=0 maxholewidth=2 maxwidth=2
RoutingVias "Schematic Routing Via Style_3" [InComponent('H6')] p8: holewidth=0 width=0 viastyle="Through Hole" minholewidth=0 minwidth=0 maxholewidth=2 maxwidth=2
RoutingVias "Schematic Routing Via Style_2" [InComponent('H4')] p9: holewidth=0 width=0 viastyle="Through Hole" minholewidth=0 minwidth=0 maxholewidth=2 maxwidth=2
RoutingVias "Schematic Routing Via Style_1" [InComponent('H2')] p10: holewidth=0 width=0 viastyle="Through Hole" minholewidth=0 minwidth=0 maxholewidth=2 maxwidth=2
RoutingVias "Schematic Routing Via Style" [InComponent('H3')] p11: holewidth=0 width=0 viastyle="Through Hole" minholewidth=0 minwidth=0 maxholewidth=2 maxwidth=2
ShortCircuit "GND to PVSS" [InNet('PVSS1') or InNet('PVSS2') vs InNet('GND')] p1: allowed=TRUE
ShortCircuit P11_P12 [InComponent('P11') vs InComponent('P12')] p2: allowed=TRUE
ShortCircuit [All] p3: allowed=FALSE
SolderMaskExpansion SolderMaskExpansion_Comp1 [HasFootprint('BGA98C35P10X10_367X385X86') or HasFootprint('AQFN40P700X700X85_HS-99N') or HasFootprint('XFDFN40P180X120X40-8M')] p1: expansion=0.025 istentingtop=FALSE
SolderMaskExpansion SolderMaskExpansion_Comp2 [HasFootprint('Nordic_QFN50P500X500X90-33N') or HasFootprint('SD-80259-001')] p2: expansion=0.05 istentingtop=FALSE
SolderMaskExpansion SolderMaskExpansion_Via [IsVia] p3: expansion=0.102 istentingtop=TRUE
SolderMaskExpansion [All] p4: expansion=0.102 istentingtop=FALSE
SupplyNets "Schematic Supply Nets_6" [InNet('5V0:CONN')] p1: voltage=0.000
SupplyNets "Schematic Supply Nets_15" [InNet('VDD:IO')] p2: voltage=0.000
SupplyNets "Schematic Supply Nets_14" [InNet('VDD:SW_PU')] p3: voltage=0.000
SupplyNets "Schematic Supply Nets_11" [InNet('VDD:nRF_PMIC')] p4: voltage=0.000
SupplyNets "Schematic Supply Nets_4" [InNet('VDD:SW')] p5: voltage=0.000
SupplyNets "Schematic Supply Nets_3" [InNet('P5V0:LED')] p6: voltage=0.000
SupplyNets "Schematic Supply Nets_7" [InNet('VDD:SWD0')] p7: voltage=0.000
SupplyNets "Schematic Supply Nets_10" [InNet('VBUS:DBGR')] p8: voltage=0.000
SupplyNets "Schematic Supply Nets_2" [InNet('VDD:nRF')] p9: voltage=0.000
SupplyNets "Schematic Supply Nets_13" [InNet('VDD:DBGR')] p10: voltage=0.000
SupplyNets "Schematic Supply Nets_12" [InNet('VBUS:nRF')] p11: voltage=0.000
SupplyNets "Schematic Supply Nets_9" [InNet('P5V0')] p12: voltage=0.000
SupplyNets "Schematic Supply Nets_8" [InNet('GND')] p13: voltage=0.000
SupplyNets "Schematic Supply Nets_5" [InNet('Shield')] p14: voltage=0.000
SupplyNets "Schematic Supply Nets_1" [InNet('VBUS')] p15: voltage=0.000
Width "Antena width" [InNet('ANT')] p1: maxlimit=2 minlimit=0.1 preferedwidth=0.254
Width "RF class" [InNetClass('RF')] p2: maxlimit=0.254 minlimit=0.102 preferedwidth=0.254 toplayer_maxwidth=0.102 toplayer_prefwidth=0.102 bottomlayer_maxwidth=0.102 bottomlayer_prefwidth=0.102 impedanceprofiledriven=TRUE impedanceprofileid={1565A465-2A4E-46A6-9374-F3DA2557FCC2} impedanceprofilevalue=50.000000 minimp=50.000000 maximp=50.000000 favimp=50.000000
Width [All] p3: maxlimit=1 minlimit=0.09 preferedwidth=0.1
23 further rules are at their usual default settings.

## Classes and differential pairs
component class Switches: C61 C62 R56 SB5 TP13 TP29 TP30 TP31 TP32 TP33 TP34 U15 U16
component class nRF54: U1
net class RF: ANT ant:1 ant:2 ant:3 ant:4
differential pair class NFC: NFC
component class "Power Switch": C55 Q2 Q3 R20 R21 R22 R23 R24 SB6 SW5 TP14
component class nPM1300: C33 C34 C35 C36 C37 C38 C39 C40 C41 C42 C43 C44 C45 C46 C47 C48 C49 C50 C51 C52 C54 L5 L6 R14 R16 R17 R18 SB17 SB18 SB20 SB21 SB27 SB28 SB29 SB30 TP1 TP4 TP5 TP6 TP35 U3
component class "Current measurments": JP1 P14 R15 SB19
component class Flash: C58 SB23 SB24 U4
net class TRACE: P2.06 P2.07 P2.08 P2.09 P2.10
component class "Levelshifters and switches": C78 C79 C80 C81 C82 C83 C84 C85 C86 C87 C88 C89 Q9 R19 R36 R37 R38 R39 R40 R41 R42 R43 R44 R51 U5 U6 U7 U8 U12 U13 U14
component class pca10184_top_level: SB25 SB26
component class Misc: C56 C57 C58 LD1 LD2 LD3 LD4 Q4 Q5 Q6 Q7 R25 R26 R27 R28 R29 R30 R31 R32 R33 R34 R35 SB22 SB23 SB24 SW1 SW2 SW3 SW4 SW6 U4
component class nRF54LM20: C1 C2 C3 C4 C5 C6 C7 C8 C9 C10 C11 C12 C13 C14 C76 FB1 FB2 J1 L1 L2 L3 L4 R1 R2 R3 R4 SB1 SB2 SB3 SB4 TP3 TP11 TP12 U1 X1 X2
differential pair class nRF54: DBGR_CON J2 J3 nRF54_CON
differential pair class IMCU: DBGR DBGR_U2 USB_nRF54
net class USB: DBGR_CON_N DBGR_CON_P DBGR_N DBGR_P nRF54_CON_N nRF54_CON_P USB_nRF54_D+ USB_nRF54_D-
net class UART1: UART1_CTRL UART1_CTS_DBGR UART1_HWFC UART1_RTS_DBGR UART1_RxD_DBGR UART1_TxD_DBGR
net class UART0: UART0_CTRL UART0_CTS_DBGR UART0_HWFC UART0_RTS_DBGR UART0_RxD_DBGR UART0_TxD_DBGR
component class "Power supply": C33 C34 C35 C36 C37 C38 C39 C40 C41 C42 C43 C44 C45 C46 C47 C48 C49 C50 C51 C52 C54 C55 C59 C60 JP1 L5 L6 P14 P16 Q2 Q3 Q8 R14 R15 R16 R17 R18 R20 R21 R22 R23 R24 R52 R53 R54 R55 SB6 SB17 SB18 SB19 SB20 SB21 SB27 SB28 SB29 SB30 SB31 SW5 TP1 TP2 TP4 TP5 TP6 TP14 TP15 TP16 TP17 TP18 TP19 TP20 TP35 U3 U9
component class Mechanical: Fid1 Fid2 Fid3 H1 H2 H3 H4 H5 H6 LABEL1 LOGO1 LOGO3
component class Debugger: C15 C16 C17 C18 C19 C20 C21 C22 C23 C24 C25 C26 C27 C28 C29 C30 C31 C32 C77 FB5 J2 LD5 Q1 R5 R6 R7 R8 R9 R10 R11 R12 R13 R47 R48 R49 R50 TP7 TP8 TP9 TP10 U2 X3
component class Connectors: C63 C64 C65 C66 C67 C68 C69 C70 C71 C72 C73 C74 FB3 FB4 J3 J4 J5 P1 P2 P3 P4 P5 P6 P7 P8 P9 P10 P11 P12 P13 P17 P18 P30 P31 P32 P34 P35 R45 R46 TP21 TP22 TP23 TP24 TP25 TP26 TP27 TP28 U10 U11
differential pair nRF54_CON: +nRF54_CON_P -nRF54_CON_N
differential pair USB_nRF54: +USB_nRF54_D+ -USB_nRF54_D-
differential pair NFC: +NFC_P -NFC_N
differential pair DBGR_CON: +DBGR_CON_P -DBGR_CON_N
differential pair DBGR: +DBGR_P -DBGR_N

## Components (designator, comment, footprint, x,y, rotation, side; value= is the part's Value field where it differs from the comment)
C1 "100nF" CAPC0603X03L_C 128.903,34.877 r0 top
C2 "100nF" CAPC0603X03L_C 122.674,34.751 r90 top
C3 "2.0pF" CAPC0603X03L_C 129.688,33.976 r270 top
C4 "10µF" CAPC1005X04L 127.552,30.702 r90 top
C5 "100nF" CAPC0603X03L_C 124.046,31.414 r180 top
C6 "2.2µF" CAPC0603X03L_C 125.494,31.312 r0 top
C7 "2.2µF" CAPC0603X03L_C 124.529,29.864 r90 top
C8 "10nF" CAPC0603X03L_C 124.808,30.677 r180 top
C9 "3.9pF" CAPC0603X03L_C 128.898,32.887 r180 top
C10 "2.2µF" CAPC0603X03L_C 125.274,37.851 r270 top
C11 "4.7µF" CAPC1005X04L 124.568,37.601 r270 top
C12 "2.0pF" CAPC0603X03L_C 131.32,33.976 r270 top
C13 "N.C." CAPC0603X03L_C_NC 132.962,33.976 r270 top
C14 "2.2µF" CAPC0603X03L_C 128.903,32.371 r180 top
C15 "100nF" CAPC0603X03L_C 13.054,18.854 r180 top
C16 "100nF" CAPC0603X03L_C 15.35,14.8 r270 top
C17 "100nF" CAPC0603X03L_C 18.047,14.8 r270 top
C18 "1.0µF" CAPC1005X04L 20.325,25.55 r90 top
C19 "1.0µF" CAPC1005X04L 22.575,24.725 r0 top
C20 "2.2nF" CAPC0603X03L_C 24.25,22.325 r90 top
C21 "100nF" CAPC0603X03L_C 20.85,14.8 r270 top
C22 "100nF" CAPC0603X03L_C 23.858,20.067 r0 top
C23 "100nF" CAPC0603X03L_C 23.7,22.325 r270 top
C24 "100nF" CAPC0603X03L_C 23.953,24.091 r0 top
C25 "1.0µF" CAPC1005X04L 18.648,25.63 r0 top
C26 "2.2µF" CAPC1608X06L 13.05,20.443 r90 top
C27 "4.7µF" CAPC1608X06L 13.297,28.121 r180 top
C28 "100nF" CAPC0603X03L_C 13.687,27.31 r180 top
C29 "4.7µF" CAPC1608X06L 15.1,25.8 r90 top
C30 "4.7µF" CAPC1608X06L 16.2,25.8 r90 top
C31 "100nF" CAPC0603X03L_C 21.069,23.975 r0 top
C32 "1.0µF" CAPC1005X04L 18.25,24.78 r0 top
C33 "10µF" CAPC1608X06L 18.451,42.752 r90 top
C34 "4.7µF" CAPC1005X04L_C2 11.55,47 r0 top
C35 "100nF" CAPC0603X03L_C 11.55,46.325 r0 top
C36 "4.7µF" CAPC1005X04L_C2 13.725,47.2 r0 top
C37 "100nF" CAPC0603X03L_C 13.75,47.899 r0 top
C38 "4.7µF" CAPC1005X04L_C2 12.968,53.1 r90 top
C39 "1.0µF" CAPC1005X04L 13.731,45.475 r0 top
C40 "10µF" CAPC1608X06L 23.327,46.672 r90 top
C41 "10µF" CAPC1608X06L 23.327,49.222 r270 top
C42 "1.0nF" CAPC0603X03L_C 24.512,48.347 r180 top
C43 "1.0nF" CAPC0603X03L_C 24.512,47.547 r180 top
C44 "10µF" CAPC1608X06L 13.6,48.725 r0 top
C45 "10µF" CAPC1608X06L 13.6,49.85 r0 top
C46 "10µF" CAPC1608X06L 22.65,44.75 r180 top
C47 "100nF" CAPC0603X03L_C 26.163,47.547 r0 top
C48 "10µF" CAPC1608X06L 23.327,51.96 r90 top
C49 "100nF" CAPC0603X03L_C 26.167,48.342 r0 top
C50 "10µF" CAPC1608X06L 19.625,42.752 r90 top
C51 "10µF" CAPC1608X06L 17.225,42.752 r90 top
C52 "10µF" CAPC1608X06L 20.825,42.752 r90 top
C54 "100nF" CAPC0603X03L_C 19.275,51.85 r90 top
C55 "4.7µF" CAPC1608X06L 8.35,51 r90 top
C56 "300pF" CAPC1005X04L 142.9,54.7 r0 top
C57 "300pF" CAPC1005X04L 140.9,54.7 r0 top
C58 "100nF" CAPC0603X03L_C 97.519,26.364 r0 top
C59 "100nF" CAPC0603X03L_C 37.477,45.532 r270 top
C60 "100nF" CAPC0603X03L_C 32.665,44.201 r90 top
C61 "100nF" CAPC0603X03L_C 105.423,31.977 r90 top
C62 "100nF" CAPC0603X03L_C 94.168,27.266 r180 top
C63 "100nF" CAPC0603X03L_C 10.725,44.275 r180 top
C64 "1.0µF" CAPC1005X04L 10.2,41.8 r180 top
C65 "10nF" CAPC0603X03L_C 11.2,43.1 r180 top
C66 "100nF" CAPC0603X03L_C 11.2,42.52 r180 top
C67 "10nF" CAPC1005X04L 2.256,33.328 r270 top
C68 "10nF" CAPC1005X04L 3.17,33.328 r270 top
C69 "100nF" CAPC0603X03L_C 11,29.4 r180 top
C70 "1.0µF" CAPC1005X04L 10.195,26.568 r180 top
C71 "10nF" CAPC0603X03L_C 10.139,25.42 r180 top
C72 "100nF" CAPC0603X03L_C 10.139,25.927 r180 top
C73 "10nF" CAPC1005X04L 2.256,30.175 r90 top
C74 "10nF" CAPC1005X04L 3.17,30.175 r90 top
C76 "1.0pF" CAPC0603X03L_C 136.773,34.487 r270 top
C77 "100nF" CAPC0603X03L_C 14.35,22.775 r90 top
C78 "100nF" CAPC0603X03L_C 34.27,14.532 r90 top
C79 "100nF" CAPC0603X03L_C 29.703,13.515 r180 top
C80 "100nF" CAPC0603X03L_C 31.554,13.511 r0 top
C81 "100nF" CAPC0603X03L_C 34.27,19.659 r90 top
C82 "100nF" CAPC0603X03L_C 29.703,18.654 r180 top
C83 "100nF" CAPC0603X03L_C 31.554,18.651 r0 top
C84 "100nF" CAPC0603X03L_C 33.985,24.396 r180 top
C85 "100nF" CAPC0603X03L_C 29.704,23.655 r180 top
C86 "100nF" CAPC0603X03L_C 31.554,23.655 r0 top
C87 "1.0µF" CAPC1005X04L 33.779,25.425 r0 top
C88 "100nF" CAPC0603X03L_C 18.452,28.335 r90 top
C89 "100nF" CAPC0603X03L_C 18.183,31.151 r90 top
FB1 "120R/0.2A" INDC0603X03L_C 125.088,29.864 r90 top
FB2 "120R/0.2A" INDC0603X03L_C 128.649,31.558 r270 top
FB3 "120R/3A" INDC1608X06L 9.635,43.472 r90 top
FB4 "120R/3A" INDC1608X06L 9.787,28.241 r90 top
FB5 "120R/100MHz" INDC1005X04L_C2 13.972,29.539 r90 top
Fid1 "Fiducial mark" Fiducial 3.175,3.175 r0 top value=N.A.
Fid2 "Fiducial mark" Fiducial 133.35,2.54 r0 top value=N.A.
Fid3 "Fiducial mark" Fiducial 141.09,61.491 r0 top value=N.A.
H1 "MountingHole_NPTH" MountingHole_3.2_M3 12.6,58.5 r0 top value=MountingHole_3.2_M3
H2 "MountingHole_NPTH" MountingHole_3.2_M3 44,58.5 r0 top locked value=MountingHole_3.2_M3
H3 "MountingHole_NPTH" MountingHole_3.2_M3 113.1,58.5 r0 top locked value=MountingHole_3.2_M3
H4 "MountingHole_NPTH" MountingHole_3.2_M3 8,5 r0 top locked value=MountingHole_3.2_M3
H5 "MountingHole_NPTH" MountingHole_3.2_M3 44,5 r0 top value=MountingHole_3.2_M3
H6 "MountingHole_NPTH" MountingHole_3.2_M3 106,5 r0 top locked value=MountingHole_3.2_M3
J1 "MM8130-2600" COAXIAL-SWF 134.837,33.712 r90 top
J2 "TC2050-IDC" TC2050-IDC-NLFP 24.5,2.165 r0 top locked
J3 "USB-C 2.0" SD-80259-001 5.1,39.37 r270 top
J4 "USB-C 2.0" SD-80259-001 5.1,24.134 r270 top
J5 "FPC 0.5mm RA SMD" FPC_05P-0.5mm-RA-SMD 142.9,56 r180 top
JP1 "Shunt 2.54mm" Shunt_2.54mm_Vertical 33.012,59.765 r0 top
L1 "4.7µH" INDC1608X06L 126.586,30.448 r270 top
L2 "2.7nH" INDC0603X03L_C 128.872,33.702 r0 top
L3 "4.7nH" INDC0603X03L_C 130.505,33.7 r0 top
L4 "2.7nH" INDC0603X03L_C 132.134,33.694 r0 top
L5 "2.2µH" INDC2016X10N 25.612,46.047 r180 top
L6 "2.2µH" INDC2016X10N 25.125,50.325 r270 top
LABEL1 "12x12mm" LabelSilk_12x12 78.097,19.153 r0 top
LD1 "L0603G" LED_0603_G 119.2,48.1 r0 top
LD2 "L0603G" LED_0603_G 125.5,48.1 r0 top
LD3 "L0603G" LED_0603_G 119.2,44.4 r0 top
LD4 "L0603G" LED_0603_G 125.5,44.4 r0 top
LD5 "L0603G" LED_0603_G 25.8,10.65 r0 top
LOGO1 "WEE Symbol" WEE_3x4.5mm 5.8,56.7 r90 bottom
LOGO3 "Segger Logo S" SEGGER_LOGO_S 16,6.5 r90 bottom
P1 "Pin Hdr 2x10" HDR_2x10-SMD 63.05,50.8 r0 top locked
P2 "Pin Hdr 2x10" HDR_2x10-SMD 63.05,38.1 r0 top locked
P3 "Pin Hdr 2x10" HDR_2x10-SMD 63.05,25.4 r0 top locked
P4 "Pin Hdr 2x10" HDR_2x10-SMD 101.785,50.8 r0 top locked
P5 "Pin Hdr 2x10" HDR_2x10-SMD 101.785,38.1 r0 top locked
P6 "Pin Header 2x2 SMD" HDR_2x2-SMD 44,50.8 r0 top locked
P7 "Pin Header 2x2 SMD" HDR_2x2-SMD 44,38.1 r0 top locked
P8 "Pin Header 2x2 SMD" HDR_2x2-SMD 44,25.4 r0 top locked
P9 "Pin Header 2x2 SMD" HDR_2x2-SMD 82.735,50.8 r0 top locked
P10 "Pin Header 2x2 SMD" HDR_2x2-SMD 82.735,38.1 r0 top locked
P11 "Pin Header 2x5, 1.27mm" HDR_2x5-SMD-1.27mm-K 120.247,58.726 r0 top locked
P12 "Pin Header 2x10, 1.27mm" HDR_2x10-SMD-1.27mm-NC 123.422,58.726 r0 top locked
P13 "Pin Header 2x5, 1.27mm" HDR_2x5-SMD-1.27mm-K 15.827,3.825 r0 top
P14 "Pin List 1x3" LIST_1x3_SMD 31.753,59.696 r0 top
P16 "Pin List 1x3" LIST_1x3_SMD 18.935,59.696 r0 top
P17 "Pin Hdr 2x13" HDR_2x13-SMD 66.86,12.7 r0 top locked
P18 "Pin Header 2x2 SMD" HDR_2x2-SMD 44,12.7 r0 top locked
Q1 "RV2C010UNT2L" DFN65P100X40-3L 23.772,10.65 r0 top
Q2 "MCM2301-TP" DFN65P200X200X80_HS-6N 6.22,49.411 r90 top
Q3 "MCM2301-TP" DFN65P200X200X80_HS-6N 2.67,49.411 r90 top
Q4 "RV2C010UNT2L" DFN65P100X40-3L 117.1,48.1 r0 top
Q5 "RV2C010UNT2L" DFN65P100X40-3L 123.4,48.1 r0 top
Q6 "RV2C010UNT2L" DFN65P100X40-3L 117.1,44.4 r0 top
Q7 "RV2C010UNT2L" DFN65P100X40-3L 123.4,44.4 r0 top
Q8 "PBSS4330PA" DFN105P200X65-3N_v2 31.568,46.466 r180 top
Q9 "RV2C010UNT2L" DFN65P100X40-3L 17.66,30.176 r0 top
R1 "2R2" RESC1608X06L 123.506,38.398 r90 top
R2 "220R" RESC0603X03L_C 125.874,37.851 r270 top
R3 "N.C." RESC1005X04L_NC 143.4,53.3 r270 top
R4 "N.C." RESC1005X04L_NC 140.4,53.3 r270 top
R5 "560R" RESC0603X03L_C 27.718,10.65 r0 top
R6 "150R" RESC0603X03L_C 19.007,28.335 r90 top
R7 "100k" RESC0603X03L_C 23.85,18.275 r0 top
R8 "47R" RESC0603X03L_C 23.85,20.675 r0 top
R9 "100k" RESC0603X03L_C 16.8,12.9 r90 top
R10 "100k" RESC0603X03L_C 17.5,12.7 r90 top
R11 "2R2" RESC1608X06L 13.972,25.8 r270 top
R12 "150R" RESC0603X03L_C 19.567,28.337 r90 top
R13 "150R" RESC0603X03L_C 20.128,28.338 r90 top
R14 "0R" RESC1005X04L 13.725,46.325 r0 top
R15 "10R" RESC1005X04L 32.287,52.709 r180 top
R16 "0R" RESC1005X04L 12.1,53.1 r90 top
R17 "47k" RESC0603X03L_C 16.4,52.2 r90 top
R18 "4k7" RESC0603X03L_C 17.2,52.2 r90 top
R19 "100k" RESC0603X03L_C 34.797,14.532 r270 top
R20 "1M0" RESC0603X03L_C 5.57,47.106 r270 top
R21 "10k" RESC0603X03L_C 6.245,47.106 r270 top
R22 "10k" RESC0603X03L_C 2.675,47.106 r90 top
R23 "100k" RESC0603X03L_C 3.32,47.106 r270 top
R24 "1M0" RESC0603X03L_C 2.02,47.106 r270 top
R25 "220R" RESC0603X03L_C 121,48.1 r0 top
R26 "220R" RESC0603X03L_C 127.4,48.1 r0 top
R27 "220R" RESC0603X03L_C 121,44.4 r0 top
R28 "220R" RESC0603X03L_C 127.4,44.4 r0 top
R29 "1M0" RESC0603X03L_C 122.5,48.1 r270 top
R30 "1M0" RESC0603X03L_C 116.2,44.4 r270 top
R31 "1M0" RESC0603X03L_C 122.4,44.4 r270 top
R32 "1M0" RESC0603X03L_C 116.1,48.1 r270 top
R33 "0R" RESC1005X04L 142.4,53.3 r90 top
R34 "0R" RESC1005X04L 141.4,53.3 r90 top
R35 "100k" RESC0603X03L_C 15.76,13.125 r0 top
R36 "100k" RESC0603X03L_C 32.956,12.891 r270 top
R37 "100k" RESC0603X03L_C 34.794,19.659 r270 top
R38 "100k" RESC0603X03L_C 32.956,18.032 r270 top
R39 "100k" RESC0603X03L_C 17.601,28.904 r270 top
R40 "100k" RESC0603X03L_C 32.956,23.052 r270 top
R41 "1M0" RESC0603X03L_C 17.305,31.151 r270 top
R42 "0R" RESC1005X04L 37.335,48.393 r0 top
R43 "0R" RESC1005X04L 37.335,47.531 r0 top
R44 "0R" RESC1005X04L 39.242,48.393 r180 top
R45 "5k1" RESC0603X03L_C 10.15,37.55 r180 top
R46 "5k1" RESC0603X03L_C 10.15,36.97 r180 top
R47 "150R" RESC0603X03L_C 20.689,28.338 r90 top
R48 "150R" RESC0603X03L_C 28.893,22.731 r0 top
R49 "150R" RESC0603X03L_C 28.893,22.174 r0 top
R50 "150R" RESC0603X03L_C 28.893,21.617 r0 top
R51 "0R" RESC1005X04L 39.242,47.531 r180 top
R52 "0R" RESC0603X03L_C 33.514,47.693 r0 top
R53 "10k" RESC0603X03L_C 34.359,47.402 r90 top
R54 "0R" RESC0603X03L_C 33.514,47.116 r180 top
R55 "33k" RESC0603X03L_C 31.832,43.916 r0 top
R56 "100k" RESC0603X03L_C 95.266,27.262 r0 top
SB1 "Solderbridge" Solderbridge_Shorted 124.172,26 r90 top net-tie
SB2 "Solderbridge" Solderbridge_Shorted 122.772,26 r90 top net-tie
SB3 "Solderbridge" Solderbridge 124.172,24.3 r270 top
SB4 "Solderbridge" Solderbridge 122.772,24.3 r270 top
SB5 "Solderbridge" Solderbridge_Shorted 94.981,26.202 r90 top net-tie
SB6 "Solderbridge" Solderbridge_Shorted_Power 1.057,47.077 r270 top net-tie
SB17 "Solderbridge" Solderbridge 10.65,51.55 r0 top
SB18 "Solderbridge" Solderbridge_Shorted_Power 13.121,51.575 r0 top net-tie
SB19 "Solderbridge" Solderbridge 34.5,52.75 r180 top
SB20 "Solderbridge" Solderbridge 34.5,51.25 r180 top
SB21 "Solderbridge" Solderbridge 34.5,49.75 r180 top
SB22 "Solderbridge" Solderbridge 12.35,12.55 r0 top
SB23 "Solderbridge" Solderbridge_Shorted 96.891,25.338 r0 top net-tie
SB24 "Solderbridge" Solderbridge 96.891,23.738 r0 top
SB25 "Solderbridge" Solderbridge 12.35,11.05 r180 top
SB26 "Solderbridge" Solderbridge_Shorted 12.35,9.55 r0 top net-tie
SB27 "Solderbridge" Solderbridge 15.67,43.2 r90 top
SB28 "Solderbridge" Solderbridge_Shorted 15.67,43.9 r270 top net-tie
SB29 "Solderbridge" Solderbridge_Shorted 15.67,41.8 r90 top net-tie
SB30 "Solderbridge" Solderbridge 15.67,42.5 r270 top
SB31 "Solderbridge" Solderbridge_Shorted_Power 21.5,55.4 r180 top net-tie
SW1 "PB SW" Switch-PB-6.2x6.3mm-SMD 117.323,15.85 r0 top locked
SW2 "PB SW" Switch-PB-6.2x6.3mm-SMD 127.584,15.85 r0 top locked
SW3 "PB SW" Switch-PB-6.2x6.3mm-SMD 117.323,6.35 r0 top locked
SW4 "PB SW" Switch-PB-6.2x6.3mm-SMD 127.584,6.35 r0 top locked
SW5 "Switch" JS102011JAQN 4.7,57.9 r270 top
SW6 "PB SW" Switch-PB-6.2x6.3mm-SMD 6.096,11.637 r180 top
TP1 "Ø1.5mm,SMD" TP_SMD_D1.5mm 27.889,54.915 r90 bottom
TP2 "Ø1.5mm,SMD" TP_SMD_D1.5mm 36.567,52.829 r0 top
TP3 "Ø0.7mm,SMD" TP_SMD_D0.7mm 126.58,28.507 r0 top
TP4 "Ø1.5mm,SMD" TP_SMD_D1.5mm 23.368,58.039 r180 bottom
TP5 "Ø1.5mm,SMD" TP_SMD_D1.5mm 14.529,54.306 r180 bottom
TP6 "Ø1.5mm,SMD" TP_SMD_D1.5mm 22.073,54.814 r180 bottom
TP7 "Ø1.5mm,SMD" TP_SMD_D1.5mm 29.616,4.115 r180 bottom
TP8 "Ø1.5mm,SMD" TP_SMD_D1.5mm 23.616,4.115 r180 bottom
TP9 "Ø1.5mm,SMD" TP_SMD_D1.5mm 20.616,4.115 r180 bottom
TP10 "Ø1.5mm,SMD" TP_SMD_D1.5mm 26.616,4.115 r90 bottom
TP11 "Ø0.7mm,SMD" TP_SMD_D0.7mm 123.305,30.145 r0 top
TP12 "Ø0.7mm,SMD" TP_SMD_D0.7mm 124.848,39.48 r0 top
TP13 "Ø0.7mm,SMD" TP_SMD_D0.7mm 91.892,27.335 r270 top
TP14 "Ø1.5mm,SMD" TP_SMD_D1.5mm 4.012,52.285 r90 bottom
TP15 "TP" S1751 36.17,5.192 r270 top
TP16 "Ø1.5mm,SMD" TP_SMD_D1.5mm 11.709,48.921 r180 bottom
TP17 "Ø1.5mm,SMD" TP_SMD_D1.5mm 116.116,25.302 r0 top
TP18 "Ø1.5mm,SMD" TP_SMD_D1.5mm 45.491,13.056 r180 bottom
TP19 "Ø1.5mm,SMD" TP_SMD_D1.5mm 9.246,31.75 r180 bottom
TP20 "Ø1.5mm,SMD" TP_SMD_D1.5mm 36.17,49.2 r180 bottom
TP21 "Ø1.5mm,SMD" TP_SMD_D1.5mm 13.259,38.845 r90 bottom
TP22 "Ø1.5mm,SMD" TP_SMD_D1.5mm 10.236,38.353 r90 bottom
TP23 "Ø1.5mm,SMD" TP_SMD_D1.5mm 10.236,41.353 r90 bottom
TP24 "Ø1.5mm,SMD" TP_SMD_D1.5mm 13.259,23.572 r90 bottom
TP25 "Ø1.5mm,SMD" TP_SMD_D1.5mm 10.236,26.115 r90 bottom
TP26 "Ø1.5mm,SMD" TP_SMD_D1.5mm 143.376,51.885 r90 bottom
TP27 "Ø1.5mm,SMD" TP_SMD_D1.5mm 10.226,23.115 r90 bottom
TP28 "Ø1.5mm,SMD" TP_SMD_D1.5mm 140.376,51.885 r90 bottom
TP29 "Ø0.7mm,SMD" TP_SMD_D0.7mm 91.892,29.464 r270 top
TP30 "Ø0.7mm,SMD" TP_SMD_D0.7mm 91.876,31.593 r270 top
TP31 "Ø0.7mm,SMD" TP_SMD_D0.7mm 102.808,26.146 r0 top
TP32 "Ø0.7mm,SMD" TP_SMD_D0.7mm 104.938,26.146 r0 top
TP33 "Ø0.7mm,SMD" TP_SMD_D0.7mm 107.067,26.146 r0 top
TP34 "Ø0.7mm,SMD" TP_SMD_D0.7mm 93.221,26.216 r0 top
TP35 "Ø0.7mm,SMD" TP_SMD_D0.7mm 20.761,53.497 r0 top
U1 "nRF54LM20_PAAA" BGA98C35P10X10_367X385X86 126.195,33.875 r180 top locked
U2 "nRF5340-QKAA" AQFN40P700X700X85_HS-99N 19.05,19.675 r0 top
U3 "nPM1300-QEAA" Nordic_QFN50P500X500X90-33N 19.025,48.225 r180 top
U4 "MX25R6435F" SON127P600X80_HS-9N 100.004,29.488 r180 top
U5 "TMUX1511" XQFN40P180X260X50-16N 34.87,12.006 r0 top
U6 "TMUX1511" XQFN40P180X260X50-16N 34.87,17.146 r0 top
U7 "TMUX1511" XQFN40P180X260X50-16N 34.87,22.167 r0 top
U8 "TXB0104" QFN12P40_170X200X55L50X20 19.664,30.176 r90 top
U9 "TLV271" SOT95P280X145-5N 35.083,44.866 r0 top
U10 "ECMF02-4CMX8" UFDFN50P120X250X55-8N 10.15,39.844 r0 top
U11 "ECMF02-4CMX8" UFDFN50P120X250X55-8N 10.2,23.633 r0 top
U12 "TXB0104" QFN12P40_170X200X55L50X20 30.629,12.006 r0 top
U13 "TXB0104" QFN12P40_170X200X55L50X20 30.629,17.146 r0 top
U14 "TXB0104" QFN12P40_170X200X55L50X20 30.629,22.167 r0 top
U15 "TMUX1574" XQFN40P180X260X50-16N 94.75,29.483 r180 top
U16 "TMUX1574" XQFN40P180X260X50-16N 105.223,29.495 r0 top
X1 "32MHz" BT-XTAL_2016 130.574,31.251 r90 top
X2 "32.768kHz" XTAL_2012 124.153,28.074 r0 top
X3 "32MHz" BT-XTAL_2016 26.175,23.53 r90 top

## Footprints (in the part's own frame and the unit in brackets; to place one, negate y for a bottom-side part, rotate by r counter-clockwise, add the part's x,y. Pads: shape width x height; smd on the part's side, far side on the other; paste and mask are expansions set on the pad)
AQFN40P700X700X85_HS-99N [mm] "AQFN, 98-Leads, Body 7.00x7.00mm, Pitch 0.40mm, Thermal Pad 5.4x5.0mm, IPC Medium Density"
  rect 5.4x5 smd paste-5: 104(0.2,0)
  round 0.4 smd paste+0.012: A1(-3.2,3.2) A31(3.2,3.2) AL1(-3.2,-3.2) AL31(3.2,-3.2)
  round 0.225 smd paste+0.012: A5(-2.2,3.2) A13(-0.6,3.2) A15(-0.2,3.2) A17(0.2,3.2) A19(0.6,3.2) A21(1,3.2) A23(1.4,3.2) A25(1.8,3.2) A27(2.2,3.2) AA1(-3.2,-1) AA31(3.2,-1) AB2(-2.8,-1.2) AC1(-3.2,-1.4) AC31(3.2,-1.4) AD2(-2.8,-1.6) AE1(-3.2,-1.8) AE31(3.2,-1.8) AF2(-2.8,-2) AG1(-3.2,-2.2) AG31(3.2,-2.2) AH2(-2.8,-2.4) AJ1(-3.2,-2.6) AJ31(3.2,-2.6) AK2(-2.8,-2.8) AK4(-2.4,-2.8) AK6(-2,-2.8) AK8(-1.6,-2.8) AK10(-1.2,-2.8) AK12(-0.8,-2.8) AK14(-0.4,-2.8) AK16(0,-2.8) AK18(0.4,-2.8) AK20(0.8,-2.8) AK22(1.2,-2.8) AK24(1.6,-2.8) AK26(2,-2.8) AK28(2.4,-2.8) AK30(2.8,-2.8) AL3(-2.6,-3.2) AL5(-2.2,-3.2) AL7(-1.8,-3.2) AL9(-1.4,-3.2) AL11(-1,-3.2) AL13(-0.6,-3.2) AL15(-0.2,-3.2) AL17(0.2,-3.2) AL19(0.6,-3.2) AL21(1,-3.2) AL23(1.4,-3.2) AL25(1.8,-3.2) AL27(2.2,-3.2) AL29(2.6,-3.2) B2(-2.8,2.8) B4(-2.4,2.8) B6(-2,2.8) B8(-1.6,2.8) B10(-1.2,2.8) B12(-0.8,2.8) B14(-0.4,2.8) B16(0,2.8) B18(0.4,2.8) B20(0.8,2.8) B22(1.2,2.8) B24(1.6,2.8) B26(2,2.8) B28(2.4,2.8) B30(2.8,2.8) C1(-3.2,2.6) C31(3.2,2.6) D2(-2.8,2.4) E1(-3.2,2.2) E31(3.2,2.2) F2(-2.8,2) G1(-3.2,1.8) G31(3.2,1.8) H2(-2.8,1.6) J1(-3.2,1.4) J31(3.2,1.4) K2(-2.8,1.2) L1(-3.2,1) L31(3.2,1) M2(-2.8,0.8) N1(-3.2,0.6) N31(3.2,0.6) P2(-2.8,0.4) R1(-3.2,0.2) R31(3.2,0.2) T2(-2.8,0) U1(-3.2,-0.2) U31(3.2,-0.2) V2(-2.8,-0.4) W1(-3.2,-0.6) W31(3.2,-0.6) Y2(-2.8,-0.8)
  rrect15% 1.1x1 on Top Paste: ""(-1.75,-1.8) ""(-1.75,-0.6) ""(-1.75,0.6) ""(-1.75,1.8) ""(-0.45,-1.8) ""(-0.45,-0.6) ""(-0.45,0.6) ""(-0.45,1.8) ""(0.85,-1.8) ""(0.85,-0.6) ""(0.85,0.6) ""(0.85,1.8) ""(2.15,-1.8) ""(2.15,-0.6) ""(2.15,0.6) ""(2.15,1.8)
  silkscreen extent -4.17,3.23 -3.97,3.47, body extent -3.5,-3.5 3.5,3.5, height 0.85
BGA98C35P10X10_367X385X86 [mm] "BGA, 98-Leads, Body 3.67x3.85mmx0.86mm, Pitch 0.35mm"
  round 0.2 smd: A1(-1.575,1.575) A2(-1.225,1.575) A3(-0.875,1.575) A4(-0.525,1.575) A5(-0.175,1.575) A6(0.175,1.575) A7(0.525,1.575) A8(0.875,1.575) A9(1.225,1.575) A10(1.575,1.575) B1(-1.575,1.225) B2(-1.225,1.225) B3(-0.875,1.225) B4(-0.525,1.225) B5(-0.175,1.225) B6(0.175,1.225) B7(0.525,1.225) B8(0.875,1.225) B9(1.225,1.225) B10(1.575,1.225) C1(-1.575,0.875) C2(-1.225,0.875) C3(-0.875,0.875) C4(-0.525,0.875) C5(-0.175,0.875) C6(0.175,0.875) C7(0.525,0.875) C8(0.875,0.875) C9(1.225,0.875) C10(1.575,0.875) D1(-1.575,0.525) D2(-1.225,0.525) D4(-0.525,0.525) D5(-0.175,0.525) D6(0.175,0.525) D7(0.525,0.525) D8(0.875,0.525) D9(1.225,0.525) D10(1.575,0.525) E1(-1.575,0.175) E3(-0.875,0.175) E4(-0.525,0.175) E5(-0.175,0.175) E6(0.175,0.175) E7(0.525,0.175) E8(0.875,0.175) E9(1.225,0.175) E10(1.575,0.175) F1(-1.575,-0.175) F2(-1.225,-0.175) F3(-0.875,-0.175) F4(-0.525,-0.175) F5(-0.175,-0.175) F6(0.175,-0.175) F7(0.525,-0.175) F8(0.875,-0.175) F9(1.225,-0.175) F10(1.575,-0.175) G1(-1.575,-0.525) G2(-1.225,-0.525) G3(-0.875,-0.525) G4(-0.525,-0.525) G5(-0.175,-0.525) G6(0.175,-0.525) G7(0.525,-0.525) G8(0.875,-0.525) G9(1.225,-0.525) G10(1.575,-0.525) H1(-1.575,-0.875) H2(-1.225,-0.875) H3(-0.875,-0.875) H4(-0.525,-0.875) H5(-0.175,-0.875) H6(0.175,-0.875) H7(0.525,-0.875) H8(0.875,-0.875) H9(1.225,-0.875) H10(1.575,-0.875) J1(-1.575,-1.225) J2(-1.225,-1.225) J3(-0.875,-1.225) J4(-0.525,-1.225) J5(-0.175,-1.225) J6(0.175,-1.225) J7(0.525,-1.225) J8(0.875,-1.225) J9(1.225,-1.225) J10(1.575,-1.225) K1(-1.575,-1.575) K2(-1.225,-1.575) K3(-0.875,-1.575) K4(-0.525,-1.575) K5(-0.175,-1.575) K6(0.175,-1.575) K7(0.525,-1.575) K8(0.875,-1.575) K9(1.225,-1.575) K10(1.575,-1.575)
  Top Side keep-out region: -1.471,0.413 -0.975,0.413 -0.975,-0.075 -1.471,-0.075
  Top Side keep-out region: -1.112,0.775 -0.625,0.775 -0.625,0.275 -1.112,0.275
  body extent -1.84,-1.92 1.84,1.92, height 0.86
BT-XTAL_2016 [mm] "Crystal 2.0 x 1.6 mm"
  rect 0.95x0.85 smd: 1(-0.725,-0.575) 2(0.725,-0.575) 3(0.725,0.575) 4(-0.725,0.575)
  body extent -1.05,-0.85 1.05,0.85, height 0.56
CAPC0603X03L_C [mm] "Chip Capacitor, 2-Leads, Body 0.6x0.3mm, IPC High Density"
  rect 0.27x0.3 smd mask+0.05: 1(-0.285,0) 2(0.285,0)
  body extent -0.3,-0.15 0.3,0.15, height 0.3
CAPC0603X03L_C_NC [mm] "Chip Capacitor, 2-Leads, Body 0.6x0.3mm, IPC High Density"
  rect 0.27x0.3 smd mask+0.05: 1(-0.285,0) 2(0.285,0)
  silkscreen extent -0.49,-0.22 0.49,0.22
CAPC1005X04L [mm] "Chip Capacitor, 2-Leads, Body 1.0x0.5mm, IPC High Density"
  rect 0.6x0.5 smd: 1(-0.5,0) 2(0.5,0)
  body extent -0.5,-0.25 0.5,0.25, height 0.5
CAPC1005X04L_C2 [mm] "Chip Capacitor, 2-Leads, Body 1.0x0.5mm, IPC High Density"
  rect 0.425x0.5 smd mask+0.05: 1(-0.463,0) 2(0.463,0)
  body extent -0.5,-0.25 0.5,0.25, height 0.5
CAPC1608X06L [mm] "Chip Capacitor, 2-Leads, Body 1.6x0.8mm, IPC High Density"
  rect 0.75x0.8 smd: 1(-0.675,0) 2(0.675,0)
  body extent -0.8,-0.4 0.8,0.4, height 0.8
COAXIAL-SWF [mm]
  rect 0.5x0.58 smd: 1(0,1.16) 3(0,-1.16)
  rect 0.75x0.8 smd: 2(-1.025,-0.95) 2(-1.025,0.95) 2(1.025,-0.95) 2(1.025,0.95)
  Top Side pour cut-out: -0.65,0.55 0.65,0.55 0.65,1.35 -0.65,1.35
  Top Side pour cut-out: 0.65,-0.55 -0.65,-0.55 -0.65,-1.35 0.65,-1.35
  silkscreen extent -1.25,-0.22 1.25,0.22, body extent -1.26,-1.3 1.26,1.3, height 1.55
DFN65P100X40-3L [mm] "DFN, 3-Leads, Body 0.60x1.00mm, Pitch 0.65mm, IPC High Density"
  rect 0.4x0.25 smd mask+0.05: 1(-0.35,0.225) 2(-0.35,-0.225)
  rect 0.4x0.7 smd mask+0.065: 3(0.35,0)
  body extent -0.53,-0.33 0.53,0.33, height 0.4
DFN65P200X200X80_HS-6N [mm] "DFN, 6-Leads, Body 2.00x2.00mm, Pitch 0.65mm, IPC Medium Density"
  rect 0.45x0.42 smd mask+0.055: 1(-0.905,0.65) 2(-0.905,0) 3(-0.905,-0.65) 4(0.905,-0.65) 5(0.905,0) 6(0.905,0.65)
  rect 0.92x0.71 smd mask+0.055: 3(0,-0.475) 6(0,0.475)
  body extent -1.05,-1.05 1.05,1.05, height 0.65
DFN105P200X65-3N_v2 [mm] "DFN, 3-Leads, Body 2.00x2.00mm, Pitch 1.05mm, IPC Medium Density"
  rect 0.5x0.4 smd: 1(-0.8,0.65) 2(-0.8,-0.65)
  rect 1.1x1.6 smd: 3(0.25,0)
  silkscreen extent -1.2,-0.13 -1.06,1.36, body extent -1,-1 1,1, height 0.65
Fiducial [mm] "Fiducial Mark"
  round 1 smd paste-2539.97 mask+0.5: 0(0,0)
  round 1 smd far side paste-2539.97 mask+0.5: 0(0,0)
  Top Side keep-out circle w0.01: c0,0 r1
  Bottom Side keep-out circle w0.01: c0,0 r1
FPC_05P-0.5mm-RA-SMD [mm] "FPC, 5-Leads, Pitch 0,5mm"
  rect 0.6x2.6 smd: 0(-0.9,-2.3) 0(2.9,-2.3)
  rect 0.3x0.8 smd mask+0.05: 1(0,0) 2(0.5,0) 3(1,0) 4(1.5,0) 5(2,0)
  silkscreen extent -1.38,-3.93 3.38,0.08, body extent -1.3,-3.85 3.3,0.2, height 1.2
HDR_2x2-SMD [mil] "Board-Board Conn, Header, 4-way, 2-row"
  rect 40x113 smd: 1(-50,-100) 2(-50,100) 3(50,-100) 4(50,100)
  silkscreen extent -105,-135 100,100, body extent -100,-148 100,148, height 382
HDR_2x5-SMD-1.27mm-K [mm] "SMT MICRO HEADER, (1,27) .050\" Keying Shroud"
  rect 0.76x2.4 smd: 1(-2.54,-1.95) 2(-2.54,1.95) 3(-1.27,-1.95) 4(-1.27,1.95) 5(0,-1.95) 6(0,1.95) 7(1.27,-1.95) 8(1.27,1.95) 9(2.54,-1.95) 10(2.54,1.95)
  silkscreen extent -3.56,-2.38 3.25,1.75
HDR_2x10-SMD [mil] "Board-Board Conn, Header, 20-way, 2-row"
  rect 40x113 smd: 1(-450,-100) 2(-450,100) 3(-350,-100) 4(-350,100) 5(-250,-100) 6(-250,100) 7(-150,-100) 8(-150,100) 9(-50,-100) 10(-50,100) 11(50,-100) 12(50,100) 13(150,-100) 14(150,100) 15(250,-100) 16(250,100) 17(350,-100) 18(350,100) 19(450,-100) 20(450,100)
  silkscreen extent -505,-135 500,100, body extent -500,-148 500,148, height 382
HDR_2x10-SMD-1.27mm-NC [mm] "SMT MICRO HEADER, (1,27) .050\""
  rect 0.76x2.4 smd: 1(-5.715,-1.95) 2(-5.715,1.95) 3(-4.445,-1.95) 4(-4.445,1.95) 5(-3.175,-1.95) 6(-3.175,1.95) 7(-1.905,-1.95) 8(-1.905,1.95) 9(-0.635,-1.95) 10(-0.635,1.95) 11(0.635,-1.95) 12(0.635,1.95) 13(1.905,-1.95) 14(1.905,1.95) 15(3.175,-1.95) 16(3.175,1.95) 17(4.445,-1.95) 18(4.445,1.95) 19(5.715,-1.95) 20(5.715,1.95)
  silkscreen extent -6.73,-2.38 6.43,1.75
HDR_2x13-SMD [mil] "Board-Board Conn, Header, 26-way, 2-row"
  rect 40x113 smd: 1(-600,-100) 2(-600,100) 3(-500,-100) 4(-500,100) 5(-400,-100) 6(-400,100) 7(-300,-100) 8(-300,100) 9(-200,-100) 10(-200,100) 11(-100,-100) 12(-100,100) 13(0,-100) 14(0,100) 15(100,-100) 16(100,100) 17(200,-100) 18(200,100) 19(300,-100) 20(300,100) 21(400,-100) 22(400,100) 23(500,-100) 24(500,100) 25(600,-100) 26(600,100)
  silkscreen extent -655,-135 643,100, body extent -650,-152 650,152, height 390
INDC0603X03L_C [mm] "Chip Inductor, 2-Leads, Body 0.6x0.3mm, IPC High Density"
  rect 0.27x0.3 smd: 1(-0.285,0) 2(0.285,0)
  body extent -0.3,-0.15 0.3,0.15, height 0.3
INDC1005X04L_C2 [mm] "Chip Inductor, 2-Leads, Body 1.0x0.5mm, IPC High Density"
  rect 0.4x0.5 smd mask+0.05: 1(-0.4,0) 2(0.4,0)
  body extent -0.5,-0.25 0.5,0.25, height 0.5
INDC1608X06L [mm] "Chip Inductor, 2-Leads, Body 1.6x0.8mm, IPC High Density"
  rect 0.75x0.8 smd: 1(-0.675,0) 2(0.675,0)
  body extent -0.8,-0.4 0.8,0.4, height 0.8
INDC2016X10N [mm] "Chip Inductor, 2-Leads, Body 2.00x1.60mm, IPC Medium Density"
  rect 1.13x1.82 smd: 1(-0.885,0) 2(0.885,0)
  body extent -1,-0.8 1,0.8, height 1
JS102011JAQN [mm] "Slide Switches - DPDT, SMD, ON-ON"
  round 0.9 hole 0.9 unplated mask+0: 0(-3.4,0) 0(3.4,0)
  rect 0.5x0.5 smd: 1(-2.5,-1.2) 3(2.5,-1.2) 4(-2.5,1.2) 6(2.5,1.2)
  rect 1x1.6 smd: 2(0,-1.2) 5(0,1.2)
  Top Side region: -3,0.562 -2.838,0.4 -2,0.4 -2,2 -3,2
  Top Side region: -3,-0.562 -2.838,-0.4 -2,-0.4 -2,-2 -3,-2
  Top Side region: 3,0.562 2.838,0.4 2,0.4 2,2 3,2
  Top Side region: 3,-0.562 2.838,-0.4 2,-0.4 2,-2 3,-2
  silkscreen extent -4.5,-3.8 4.5,1.75, body extent -4.25,-3.75 4.25,1.75, height 3.5
LabelSilk_12x12 [mm] "PCA version label, stick-on, 12x12mm"
  silkscreen extent 0,0 12,12, body extent 0,0 12,12, height 0.05
LED_0603_G [mil] "SMD Super Bright LED, GREEN"
  rect 30x32 smd: 1(-27.5,0) 2(27.5,0)
  body extent -32,-16 32,16, height 24
LIST_1x3_SMD [mm] "Pin List, 2.54mm, SMD"
  rect 1.02x2.19 smd: 1(0,-1.465) 1(0,1.465) 2(2.54,-1.465) 2(2.54,1.465) 3(5.08,-1.465) 3(5.08,1.465)
  silkscreen extent -1.27,-1.27 6.35,1.27, body extent -1.27,-2.5 6.35,2.5, height 9.82
MountingHole_3.2_M3 [mm] "Mounting hole, 3.2mm, M3,no annular"
  round 3.2 hole 3.2 unplated mask+0: ""(0,0)
Nordic_QFN50P500X500X90-33N [mm] "QFN32 5x5x0.85mm, 0.5mm pitch - Medium Density"
  oval 0.85x0.3 smd: 1(-2.45,1.75) 2(-2.45,1.25) 3(-2.45,0.75) 4(-2.45,0.25) 5(-2.45,-0.25) 6(-2.45,-0.75) 7(-2.45,-1.25) 8(-2.45,-1.75) 17(2.45,-1.75) 18(2.45,-1.25) 19(2.45,-0.75) 20(2.45,-0.25) 21(2.45,0.25) 22(2.45,0.75) 23(2.45,1.25) 24(2.45,1.75)
  oval 0.3x0.85 smd: 9(-1.75,-2.45) 10(-1.25,-2.45) 11(-0.75,-2.45) 12(-0.25,-2.45) 13(0.25,-2.45) 14(0.75,-2.45) 15(1.25,-2.45) 16(1.75,-2.45) 25(1.75,2.45) 26(1.25,2.45) 27(0.75,2.45) 28(0.25,2.45) 29(-0.25,2.45) 30(-0.75,2.45) 31(-1.25,2.45) 32(-1.75,2.45)
  rect 3.5x3.5 smd: 33(0,0)
  silkscreen extent -3.43,-2.57 2.57,2.62, body extent -2.5,-2.5 2.5,2.5, height 0.9
QFN12P40_170X200X55L50X20 [mm] "QFN, 12-Leads, Body 2,1x1,8mm (max), Pitch 0,40mm, IPC Low Density"
  rrect50% 0.72x0.25 smd mask+0.04: 1(-0.64,0.8) 2(-0.64,0.4) 3(-0.64,0) 4(-0.64,-0.4) 5(-0.64,-0.8) 7(0.64,-0.8) 8(0.64,-0.4) 9(0.64,0) 10(0.64,0.4) 11(0.64,0.8)
  rrect50% 0.25x0.72 smd mask+0.04: 6(0,-0.85) 12(0,0.85)
  silkscreen extent -0.99,1.38 -0.79,1.56, body extent -0.85,-1 0.85,1, height 0.55
RESC0603X03L_C [mm] "Chip Resistor, 2-Leads, Body 0.6x0.3mm, IPC High Density"
  rect 0.27x0.3 smd: 1(-0.285,0) 2(0.285,0)
  body extent -0.3,-0.15 0.3,0.15, height 0.23
RESC1005X04L [mm] "Chip Resistor, 2-Leads, Body 1.0x0.5mm, IPC High Density"
  rect 0.6x0.55 smd mask+0.05: 1(-0.5,0) 2(0.5,0)
  body extent -0.5,-0.25 0.5,0.25, height 0.3
RESC1005X04L_NC [mm] "Chip Resistor, 2-Leads, Body 1.0x0.5mm, IPC High Density"
  rect 0.6x0.55 smd mask+0.05: 1(-0.5,0) 2(0.5,0)
RESC1608X06L [mm] "Chip Resistor, 2-Leads, Body 1.6x0.8mm, IPC High Density"
  rect 0.8x0.85 smd: 1(-0.7,0) 2(0.7,0)
  body extent -0.8,-0.4 0.8,0.4, height 0.4
S1751 [mm]
  rect 3.45x1.85 smd: 1(0,0)
  silkscreen extent -2.04,-1.25 2.06,1.25, body extent -1.67,-0.8 1.58,0.85, height 2.05
SD-80259-001 [mm] "USB TYPE C RECEPTACLE, 16 PIN"
  round 0.6 hole 0.6 unplated: 0(-2.89,1.315) 0(2.89,1.315)
  rect 0.6x1.14 smd: A1(-3.2,2.385) A4(-2.4,2.385) A9(2.4,2.385) A12(3.2,2.385)
  rect 0.3x1.14 smd: A5(-1.25,2.385) A6(-0.25,2.385) A7(0.25,2.385) A8(1.25,2.385) B5(1.75,2.385) B6(0.75,2.385) B7(-0.75,2.385) B8(-1.75,2.385)
  oval 0.9x2 hole 0.6 slot 1.7 at 90 deg: SHLD(-4.325,1.795) SHLD(4.325,1.795)
  oval 0.9x1.7 hole 0.6 slot 1.4 at 90 deg: SHLD(-4.325,-2.385) SHLD(4.325,-2.385)
  oval 0.9x2 on Top Paste: ""(-4.32,1.795) ""(4.32,1.795)
  oval 0.9x1.7 on Top Paste: ""(-4.32,-2.385) ""(4.32,-2.385)
  silkscreen extent -4.33,-4.48 4.33,0.46, body extent -4.48,-4.98 4.48,2.74, height 3.26
SEGGER_LOGO_S [mm] "Logo 7.82 mm x 3.84 mm, print overlay"
  silkscreen extent -3.91,-1.92 3.91,1.92
Shunt_2.54mm_Vertical [mm]
  body extent -2.51,-1.24 2.51,1.24, height 8.6
Solderbridge [mil]
  round 1 smd paste-99999: 1(-13.78,0) 2(13.78,0)
  Top Side region: -7.49,19.36 -15.76,15.74 -21.55,8.8 -23.62,0 -23.62,0 -21.55,-8.79 -15.76,-15.74 -7.49,-19.36 -7.49,-19.36 -6.18,-19.31 -5.02,-18.71 -4.22,-17.68 -3.94,-16.4 -3.94,-16.4 -3.94,16.4 -4.22,17.68 -5.02,18.71 -6.18,19.31 -7.49,19.36
  Top Side region: 7.49,-19.36 15.76,-15.74 21.55,-8.8 23.62,0 23.62,0 21.55,8.79 15.76,15.74 7.49,19.36 7.49,19.36 6.18,19.31 5.02,18.71 4.22,17.68 3.94,16.4 3.94,16.4 3.94,-16.4 4.22,-17.68 5.02,-18.71 6.18,-19.31 7.49,-19.36
Solderbridge_Shorted [mil]
  round 1 smd paste-99999: 1(-13.78,0) 2(13.78,0)
  Top Side region: -4.92,3.94 -4.92,-3.94 4.92,-3.94 4.92,3.94
  Top Side region: 7.49,-19.36 15.76,-15.74 21.55,-8.8 23.62,0 23.62,0 21.55,8.79 15.76,15.74 7.49,19.36 7.49,19.36 6.18,19.31 5.02,18.71 4.22,17.68 3.94,16.4 3.94,16.4 3.94,-16.4 4.22,-17.68 5.02,-18.71 6.18,-19.31 7.49,-19.36
  Top Side region: -7.49,19.36 -15.76,15.74 -21.55,8.8 -23.62,0 -23.62,0 -21.55,-8.79 -15.76,-15.74 -7.49,-19.36 -7.49,-19.36 -6.18,-19.31 -5.02,-18.71 -4.22,-17.68 -3.94,-16.4 -3.94,-16.4 -3.94,16.4 -4.22,17.68 -5.02,18.71 -6.18,19.31 -7.49,19.36
Solderbridge_Shorted_Power [mil]
  round 1 smd paste-99999: 1(-13.84,0.21) 2(13.72,0.21)
  Top Side region: -4.92,9.84 4.92,9.84 4.92,-9.84 -4.92,-9.84
  Top Side region: -7.54,19.57 -15.82,15.94 -21.61,9 -23.68,0.21 -23.68,0.21 -21.61,-8.59 -15.82,-15.53 -7.54,-19.16 -7.54,-19.16 -6.24,-19.11 -5.08,-18.51 -4.28,-17.47 -4,-16.2 -3.99,-16.2 -3.99,16.61 -4.28,17.89 -5.08,18.92 -6.24,19.52 -7.54,19.57
  Top Side region: 7.43,-19.16 15.71,-15.53 21.49,-8.59 23.56,0.21 23.56,0.21 21.49,9 15.71,15.94 7.43,19.57 7.43,19.57 6.12,19.52 4.96,18.92 4.16,17.89 3.88,16.61 3.88,16.61 3.88,-16.2 4.16,-17.47 4.96,-18.51 6.12,-19.11 7.43,-19.16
